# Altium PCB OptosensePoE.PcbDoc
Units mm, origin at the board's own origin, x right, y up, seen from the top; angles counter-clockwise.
Board outline 65 x 56 mm, 4 copper layers (Top Layer, Layer 1, Layer 2, Bottom Layer), stack 0.603 mm thick; 68 components, 52 nets, 267 pads, 672 vias.
Unrouted connection lines stored in the file: 1.
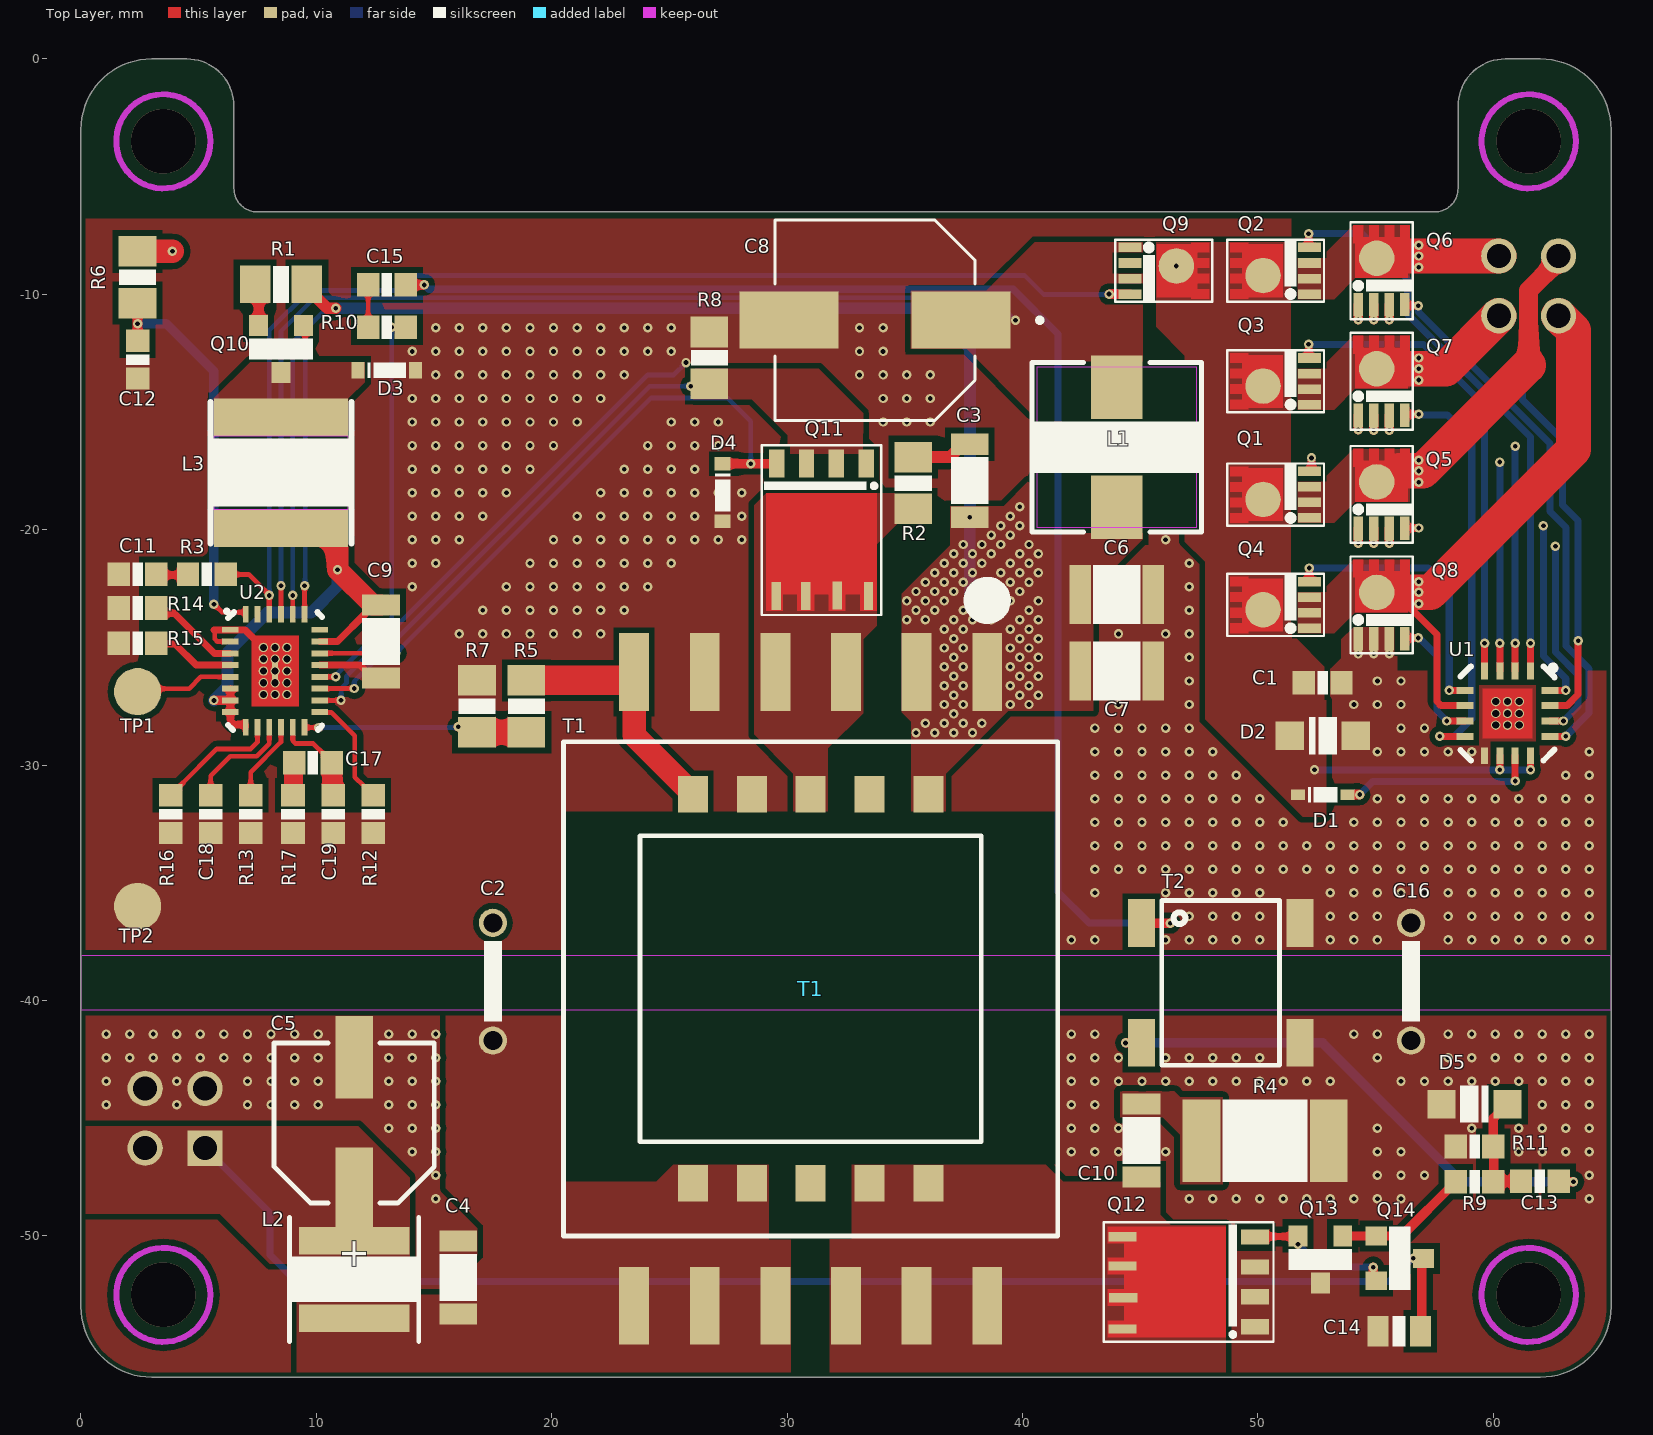
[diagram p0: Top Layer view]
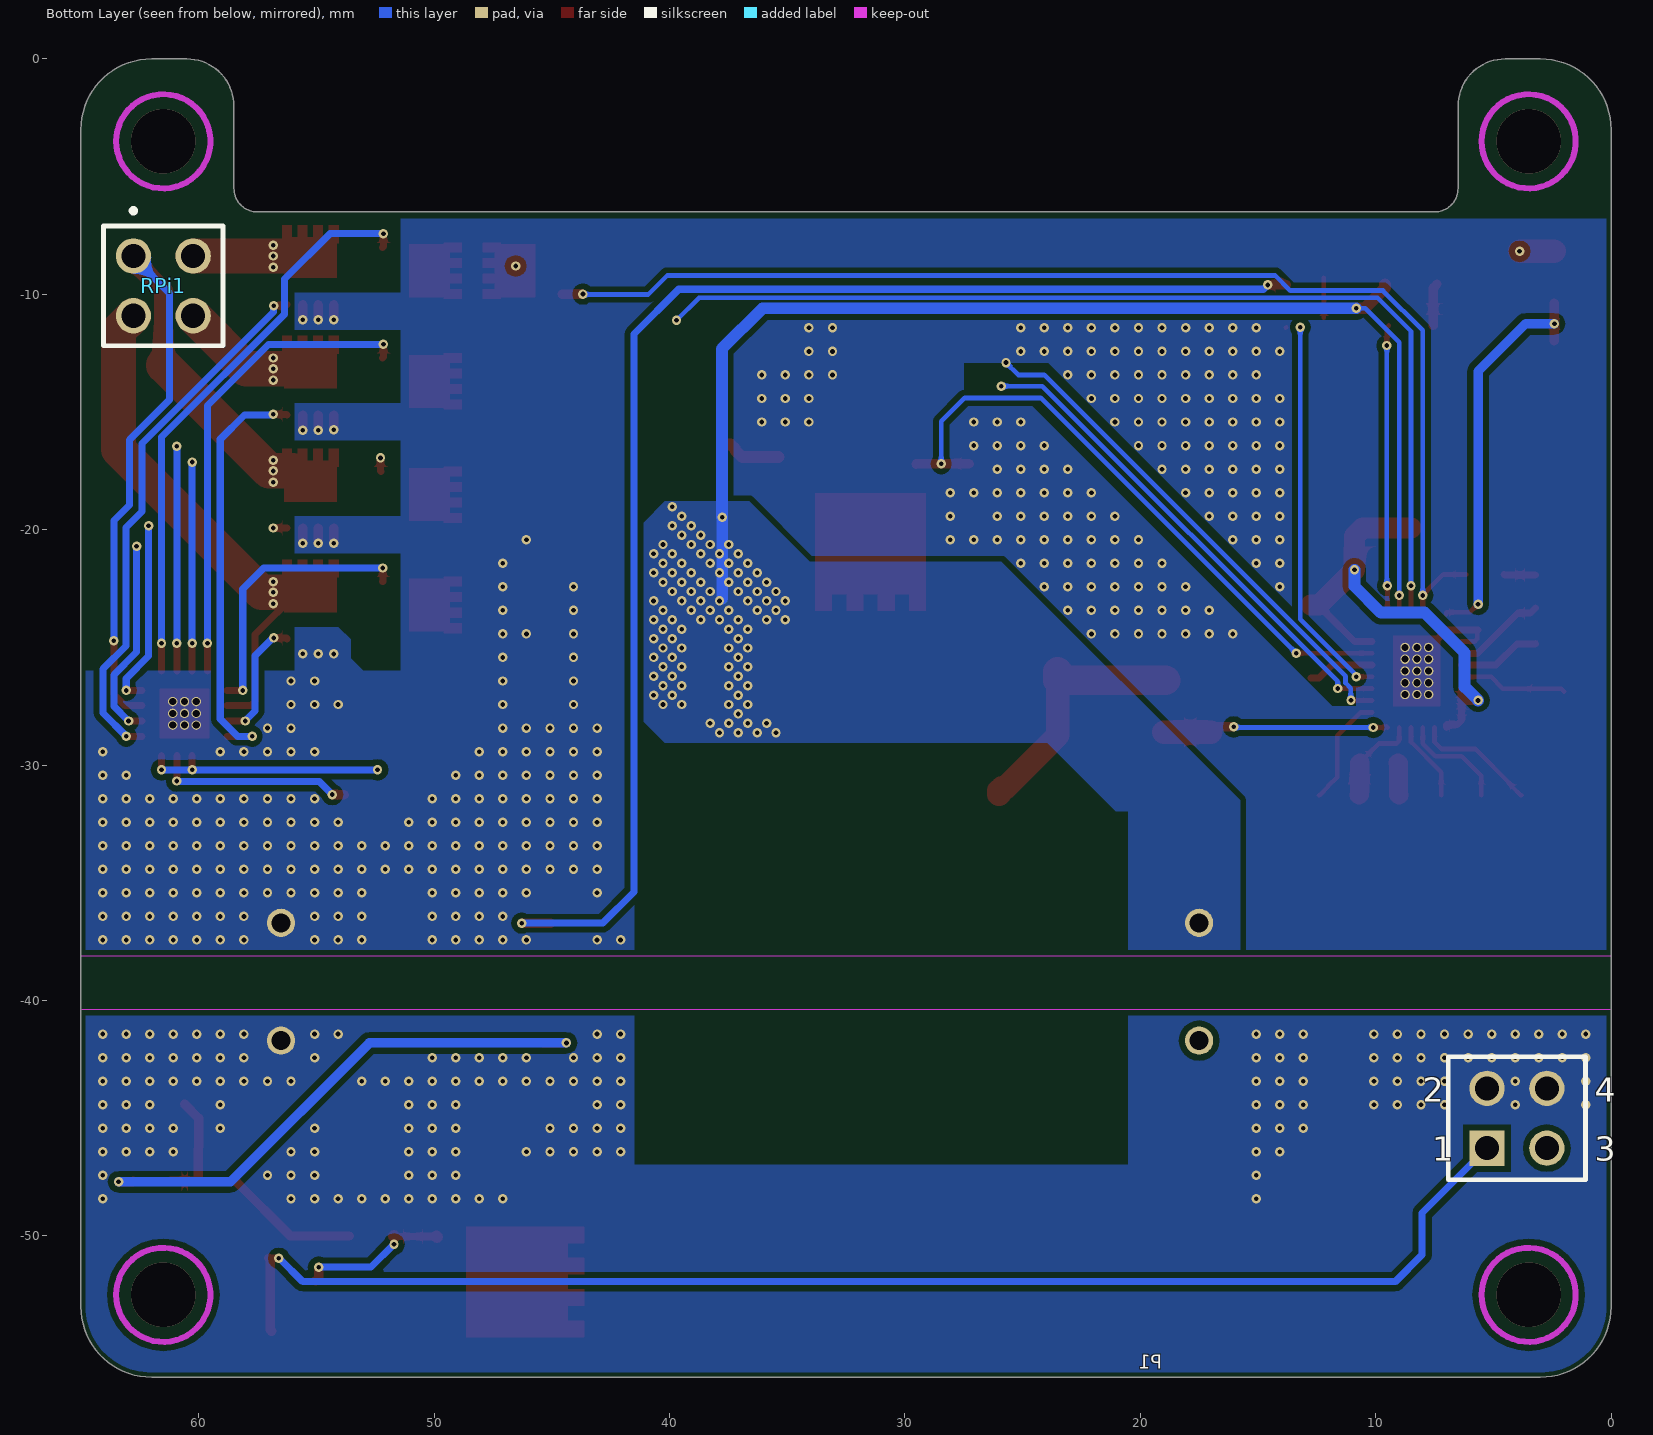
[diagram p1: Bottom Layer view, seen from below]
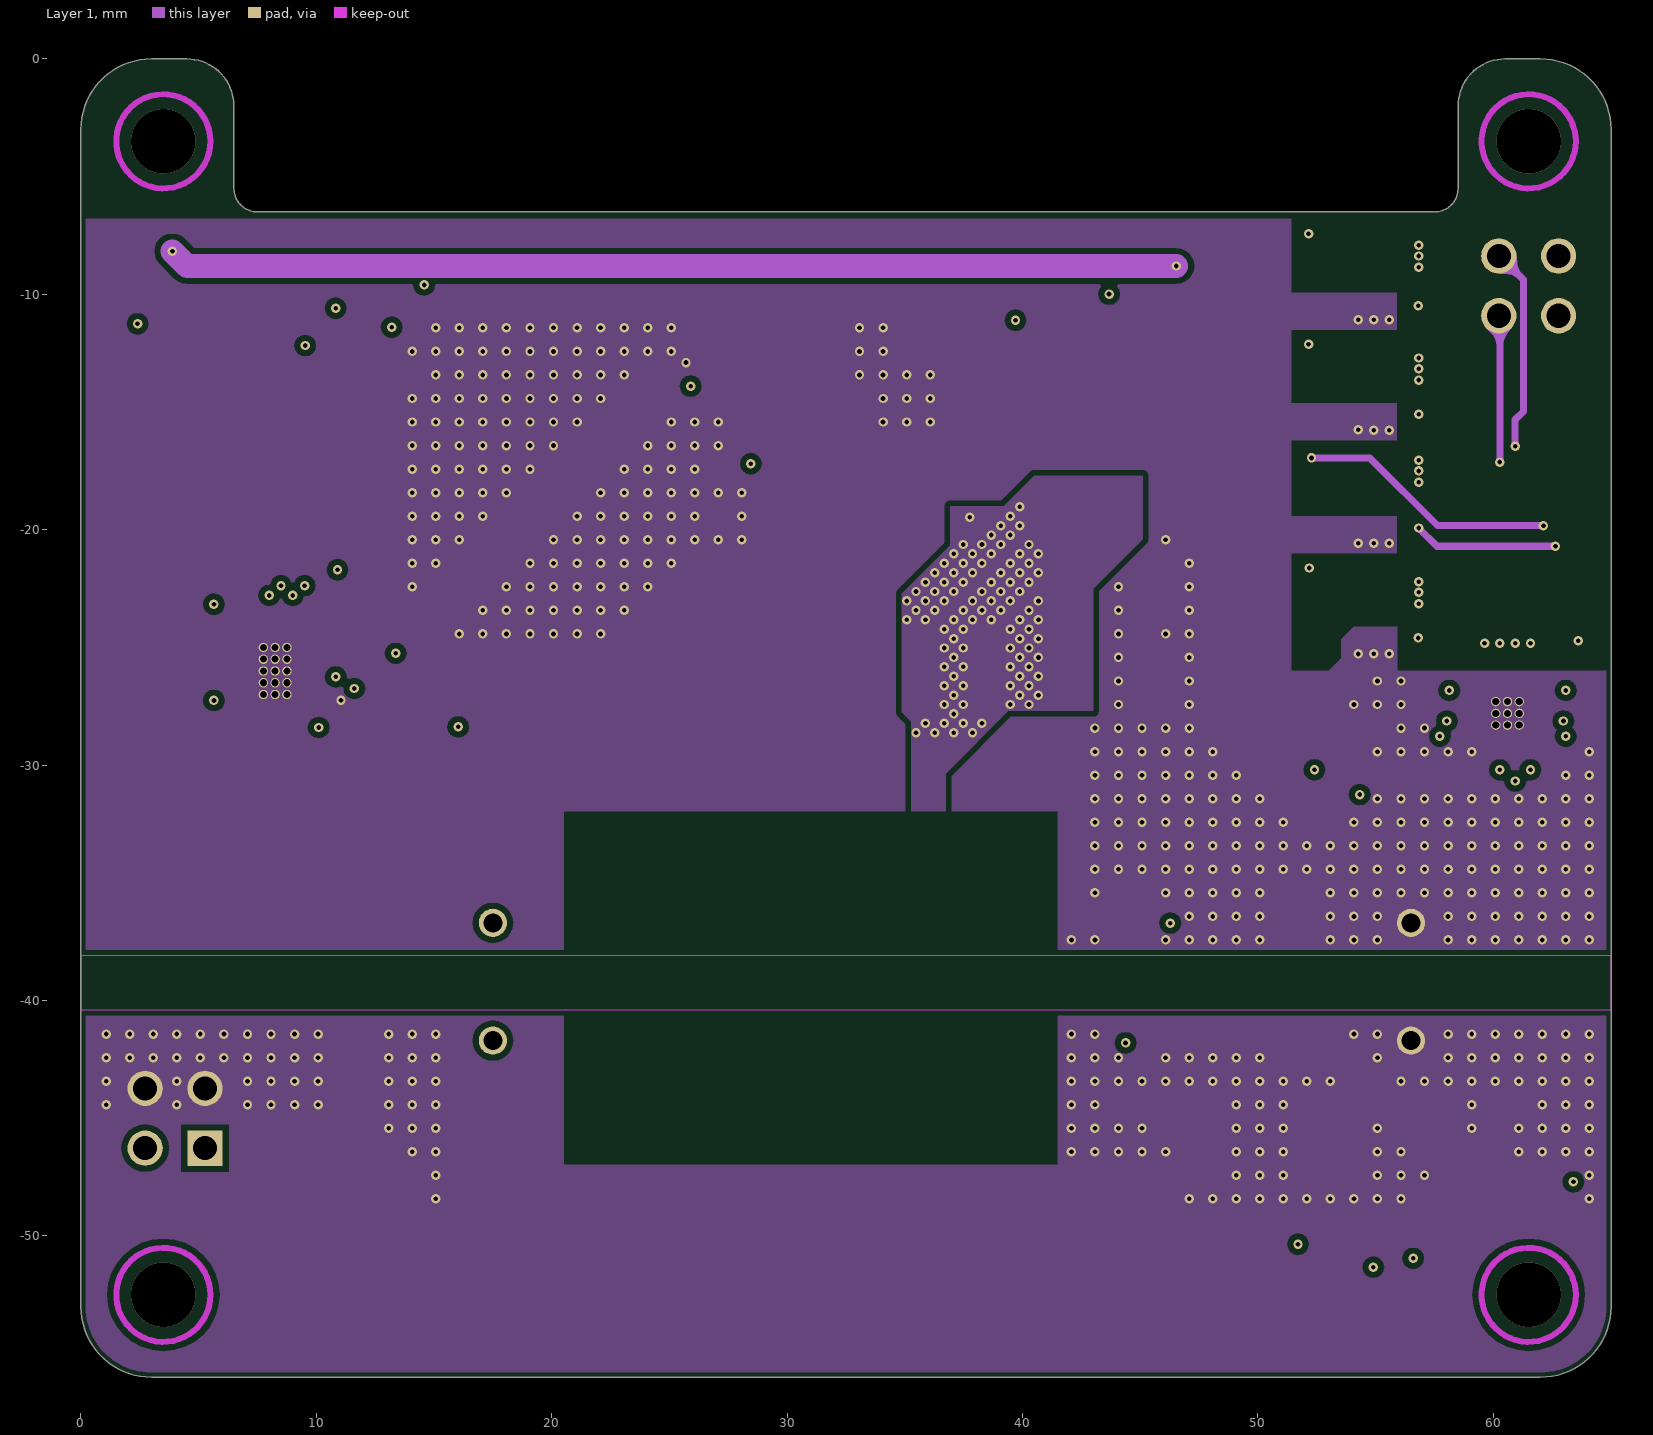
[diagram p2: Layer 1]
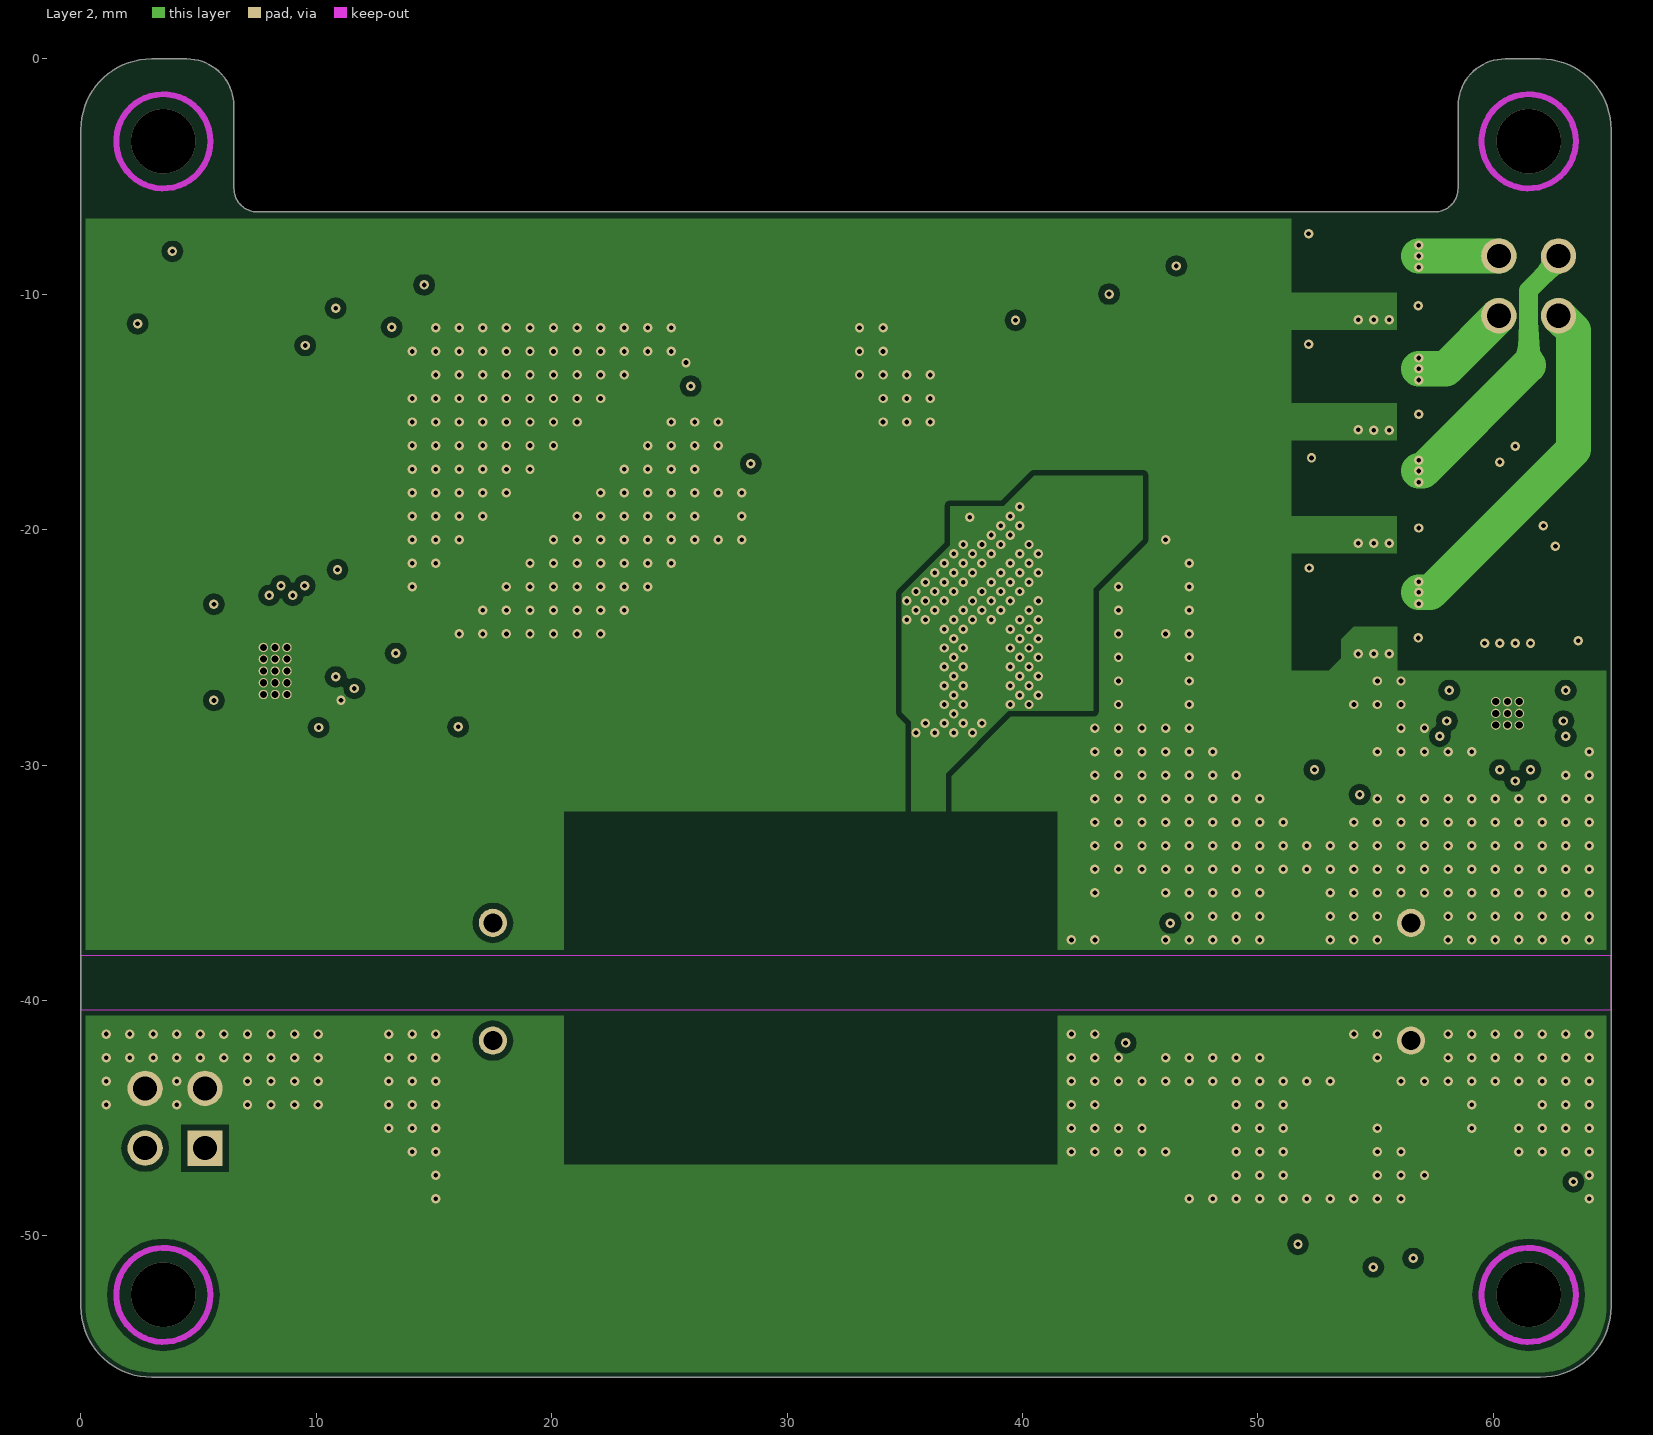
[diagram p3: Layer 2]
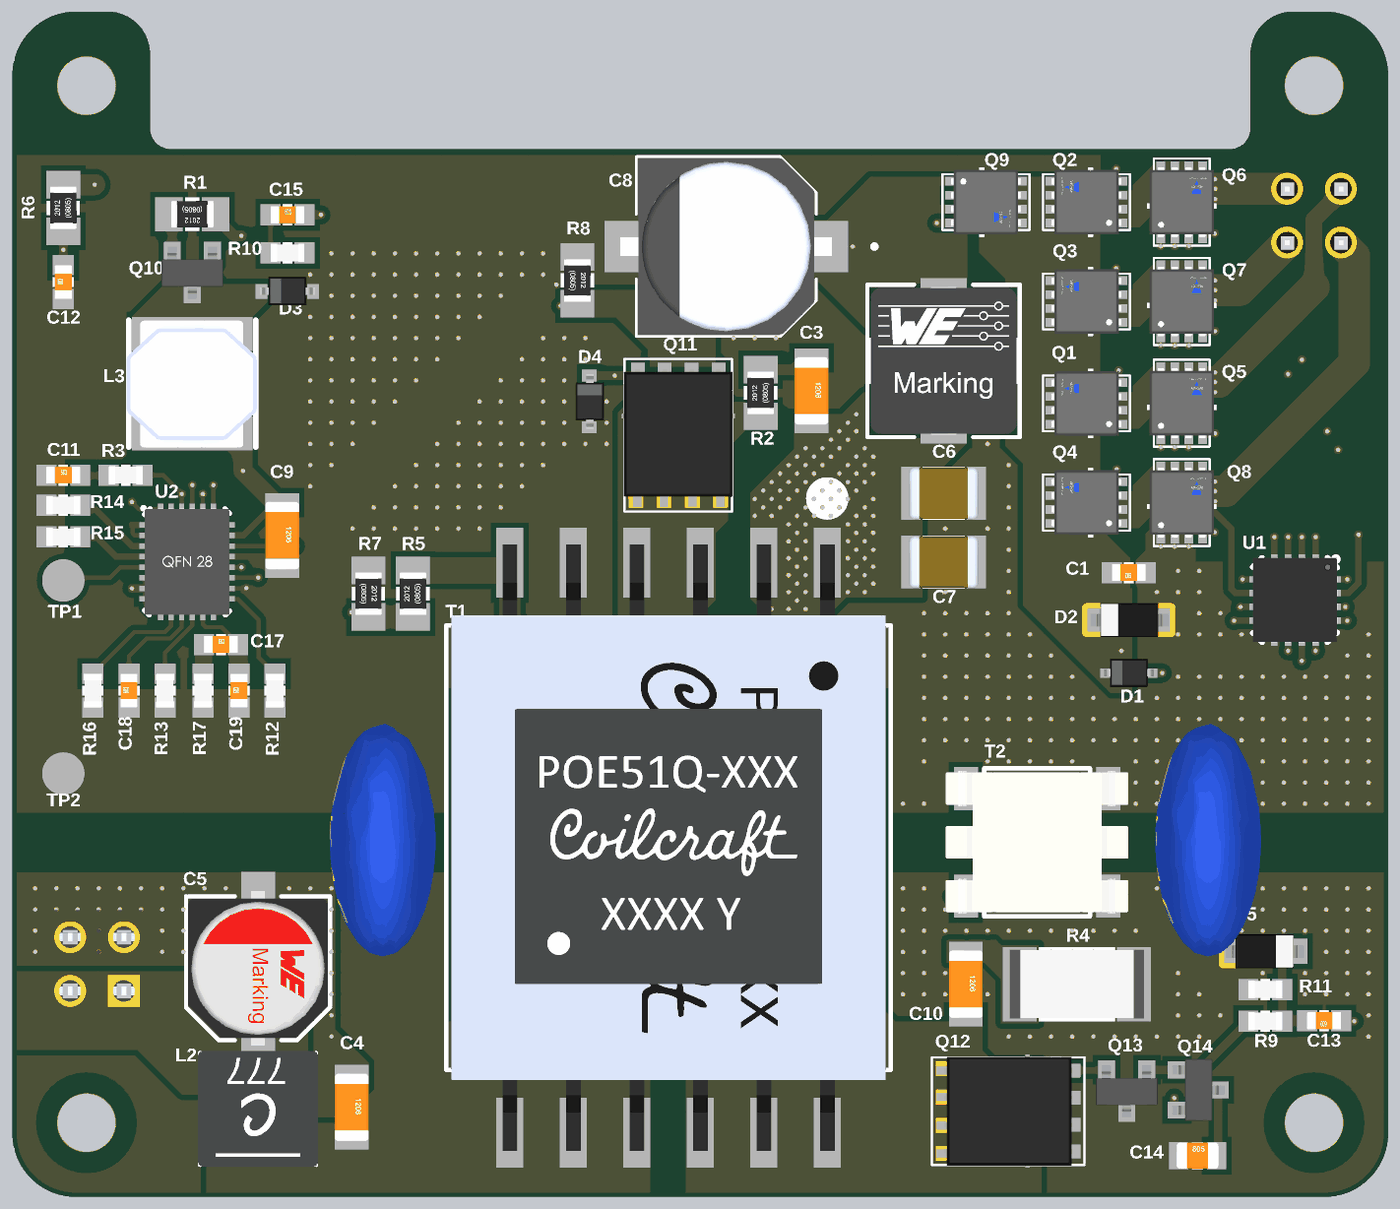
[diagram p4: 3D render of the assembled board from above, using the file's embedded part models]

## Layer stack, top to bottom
Top Solder: solder mask 0.0102, Solder Resist, Dk 3.5
Top Layer: signal copper 0.0356
Dielectric 2: core 0.0711, PP-006, Dk 4.1
Layer 1: signal copper 0.035
Dielectric 1: prepreg 0.32, FR-4, Dk 4.8
Layer 2: signal copper 0.035
Dielectric 3: core 0.0711, PP-006, Dk 4.1
Bottom Layer: signal copper 0.0356
Bottom Solder: solder mask 0.0102, Solder Resist, Dk 3.5

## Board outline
3,-56 cw(c3,-53) 0,-53 0,-3 cw(c3,-3) 3,0 4.5,0 cw(c4.5,-2) 6.5,-2 6.5,-5.5 ccw(c7.5,-5.5) 7.5,-6.5 57.5,-6.5 ccw(c57.5,-5.5) 58.5,-5.5 58.5,-2 cw(c60.5,-2) 60.5,0 62,0 cw(c62,-3) 65,-3 65,-53 cw(c62,-53) 62,-56

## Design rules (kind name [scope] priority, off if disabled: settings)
BoardOutlineClearance [All] p1: gap=0.2 ignorepadtopadclearanceinfootprint=FALSE
Clearance Clearance_VSYS [InPolygon vs InNet('VSYS')] p1: gap=0.6 ignorepadtopadclearanceinfootprint=FALSE
Clearance Clearance_2 [All] p2: gap=0.1 ignorepadtopadclearanceinfootprint=FALSE
Clearance Clearance_1 [All] p3: gap=0.1 ignorepadtopadclearanceinfootprint=FALSE
Clearance Clearance_KeepOut [All vs OnLayer('Keep-Out Layer')] p4 off: gap=1 ignorepadtopadclearanceinfootprint=FALSE except(0: Arc-Hole Track-Hole SMDPad-Hole THPad-Hole Via-Hole Fill-Hole Poly-Hole Region-Hole Text-Hole)
Clearance [All] p5: gap=0.1 ignorepadtopadclearanceinfootprint=FALSE
ComponentClearance [All] p1: gap=0 collisioncheckmode=3 verticalgap=0.254 showdistances=FALSE
FabricationTestPointUsage TestPointUsage [All] p1: valid=0 allowmultiple=FALSE
FabricationTestpoint Testpoint [All] p1: side=3 testpointundercomponent=TRUE minsize=1.016 maxsize=2.54 preferedsize=1.524 minholesize=0 maxholesize=1.016 preferedholesize=0.813 testpointgrid=0.025 allowsidetop=TRUE allowsidebottom=TRUE usegrid=TRUE gridtolerance=0
HoleSize [All] p1: absolutevalues=TRUE maxlimit=6 minlimit=0.2 maxpercent=80.000 minpercent=20.000
MinimumAnnularRing MinimumAnnularRing_Vias [isVia] p1: minimumring=0.1
MinimumAnnularRing [All] p2: minimumring=0.1
MinimumSolderMaskSliver [All] p1: minsoldermaskwidth=0
NetAntennae [All] p1 off: netantennaetolerance=0
PlaneConnect PlaneConnect_Vias [isVia] p1: planeconnectstyle=Direct reliefexpansion=0.508 reliefentries=4 reliefconductorwidth=0.254 reliefairgap=0.254
PlaneConnect [All] p2: planeconnectstyle=Direct reliefexpansion=0.508 reliefentries=4 reliefconductorwidth=0.254 reliefairgap=0.254
PolygonConnect PolygonConnect_Vias [isVia] p1: connectstyle=Direct reliefconductorwidth=0.254 reliefentries=4 polygonreliefangle="90 Angle" airgapwidth=0.254
PolygonConnect [All] p2: connectstyle=Direct reliefconductorwidth=0.254 reliefentries=4 polygonreliefangle="90 Angle" airgapwidth=0.254
RoutingVias [All] p1: holewidth=0.5 width=0.8 viastyle="Through Hole" minholewidth=0.2 minwidth=0.2 maxholewidth=0.8 maxwidth=1
SMDEntry [All] p1: side=TRUE corner=TRUE anyangle=TRUE
SMDToCorner [All] p1 off: distance=196850
SilkToSilkClearance [All] p1 off: silktosilkclearance=0.15
SilkToSolderMaskClearance SilkscreenOverComponentPads [IsPad] p1 off: minsilkscreentomaskgap=0.15 clearancetoexposedcopper=FALSE
SolderMaskExpansion [All] p1: expansion=0 istentingtop=FALSE
ViasUnderSMD [All] p1: allowed=FALSE
Width [All] p1: maxlimit=10 minlimit=0.15 preferedwidth=0.254 checkconnectedcopper=TRUE
21 further rules are at their usual default settings.

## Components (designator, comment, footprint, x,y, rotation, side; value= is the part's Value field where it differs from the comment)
C1 "47nF" C_0603 52.75,-26.5 r180 top
C2 "2.2nF" C_CK45 17.5,-36.7 r270 top
C3 "220pF" C_1206 37.757,-17.916 r270 top
C4 "10uF" C_1206 16.031,-51.769 r270 top
C5 "47uF, 35V" WCAP-ASLI_D6.3H5.5 11.606,-45.2 r270 top
C6 "2.2uF" C_1210 44,-22.75 r180 top
C7 "2.2uF" C_1210 44,-26 r180 top
C8 "10uF, 100V" CAPAE830X1080N 33.731,-11.1 r180 top
C9 "10uF" C_1206 12.75,-24.75 r270 top
C10 "330pF" C_1206 45.05,-45.95 r270 top
C11 "10nF" C_0603 2.407,-21.9 r0 top
C12 "47nF" C_0603 2.407,-12.775 r90 top
C13 "2.2nF" C_0603 61.975,-47.675 r180 top
C14 "100nF" C_0805 56,-54.05 r0 top
C15 "1uF" C_0603 13,-9.6 r0 top
C16 "2.2nF" C_CK45 56.5,-36.7 r270 top
C17 "2.2nF" C_0603 9.855,-29.896 r0 top
C18 "470nF" C_0603 5.509,-32.082 r90 top
C19 "10pF" C_0603 10.709,-32.082 r90 top
D1 "MMSZ5252BS" SOD323 52.75,-31.25 r180 top
D2 "PTVS58VS1UR" D_SOD123#1 52.75,-28.75 r180 top
D3 "BAV19WS-TP" D_SOD323 12.995,-13.225 r180 top
D4 "BAT54WS-E3-08" D_SOD323 27.257,-18.416 r90 top
D5 "BAT46W-7-F" D_SOD123#2 59.2,-44.4 r0 top
L1 "6u5" WE-HCI_7050 44,-16.5 r0 top
L1 "10uH, 3.5A" WE-HCI_7050 44,-16.5 r0 top
L2 "1.2uH" L_XAL5030 11.606,-51.844 r90 top
L3 "100uF" L_6028 8.5,-17.575 r90 top
P1 "61300421821" 61300421821 4,-45 r180 bottom locked
Q1 "SI7322ADN-T1-GE3" VISHAY_S16-2667-SINGLE_MFG 50.75,-18.509 r180 top
Q2 "SI7322ADN-T1-GE3" VISHAY_S16-2667-SINGLE_MFG 50.75,-9 r180 top
Q3 "SI7322ADN-T1-GE3" VISHAY_S16-2667-SINGLE_MFG 50.75,-13.695 r180 top
Q4 "SI7322ADN-T1-GE3" VISHAY_S16-2667-SINGLE_MFG 50.75,-23.195 r180 top
Q5 "SI7322ADN-T1-GE3" VISHAY_S16-2667-SINGLE_MFG 55.25,-18.5 r90 top
Q6 "SI7322ADN-T1-GE3" VISHAY_S16-2667-SINGLE_MFG 55.25,-9 r90 top locked
Q7 "SI7322ADN-T1-GE3" VISHAY_S16-2667-SINGLE_MFG 55.25,-13.695 r90 top
Q8 "SI7322ADN-T1-GE3" VISHAY_S16-2667-SINGLE_MFG 55.25,-23.195 r90 top
Q9 "SI7322ADN-T1-GE3" VISHAY_S16-2667-SINGLE_MFG 46,-9 r0 top
Q10 "FMMT723TA" SOT-23-3 8.5,-12.325 r180 top
Q11 "BSC190N12NS3 G" PG-TDSON-8 31.457,-20.016 r90 top
Q12 "BSC320N20NS3 G" PG-TDSON-8 47.05,-51.95 r0 top
Q13 "PBSS5140T,215" SOT-23-3 52.65,-51 r180 top
Q14 "PBSS4140T,215" SOT-23-3 56.025,-50.95 r270 top
R1 "20" R_0805 8.5,-9.575 r180 top
R2 "27" R_0805 35.357,-18.016 r90 top
R3 "3k3" R_0603 5.35,-21.9 r0 top
R4 "18" R_2512 50.3,-45.95 r180 top
R5 "7k5" R_0805 18.924,-27.5 r90 top
R6 "8R2" R_0805 2.407,-9.275 r90 top
R7 "2k" R_0805 16.822,-27.5 r270 top
R8 "40m" R_0805 26.695,-12.7 r270 top
R9 "15" R_0603 59.2,-47.7 r180 top
R10 "100" R_0603 13,-11.4 r180 top
R11 "10k" R_0603 59.2,-46.2 r0 top
R12 "24k" R_0603 12.409,-32.082 r90 top
R13 "5k23" R_0603 7.209,-32.082 r90 top
R14 "47R5" R_0603 2.407,-23.325 r0 top
R15 "35R7" R_0603 2.407,-24.825 r0 top
R16 "107k" R_0603 3.809,-32.082 r90 top
R17 "160k" R_0603 9.009,-32.082 r90 top
RPi1 "RPi" "RPi - THT Hybrid - NoneHeader" 32.5,-3.5 r180 bottom locked
T1 "POE51Q-24ED" POEXXQ-24E 31,-39.5 r270 top locked
T1 "POE300PL_24" TRANSFORMER_COILCRAFT_POE300 31,-39.5 r270 top locked
T2 "PE-68386NL" T_PE-68386NL 48.415,-39.25 r0 top
TP1 "TP" TESTPOINT#1 2.407,-26.875 r180 top
TP2 "TP" TESTPOINT#2 2.407,-35.425 r90 top
U1 "LT4321" IC_QFN_16_PLASTIC 60.6,-27.8 r270 top
U2 "LT4295" IC_QNF_28_PLASTIC 8.25,-26 r0 top locked

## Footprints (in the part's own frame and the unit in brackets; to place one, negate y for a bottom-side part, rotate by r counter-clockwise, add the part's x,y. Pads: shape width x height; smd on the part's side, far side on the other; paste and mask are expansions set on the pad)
61300421821 [mm] "Socket Header, Pitch 2.54 mm, THT, Vertical, dual row, 4p"
  rect 1.5x1.5 hole 1.02: 1(-1.27,-1.27)
  round 1.5 hole 1.02: 2(-1.27,1.27) 3(1.27,-1.27) 4(1.27,1.27)
  silkscreen extent -2.92,-2.62 2.92,2.62, body extent -2.79,-2.54 2.79,2.54, height 8.45
C_0603 [mm]
  rect 0.95x1 smd: 1(-0.8,0) 2(0.8,0)
  silkscreen extent -0.23,-0.5 0.23,0.5, body extent -0.8,-0.4 0.8,0.4, height 0.3
C_0805 [mm]
  rect 0.9x1.3 smd: 1(-0.9,0) 2(0.9,0)
  silkscreen extent -0.28,-0.65 0.28,0.65, body extent -1,-0.62 1,0.62, height 0.78
C_1206 [mm]
  rect 0.9x1.6 smd: 1(-1.55,0) 2(1.55,0)
  silkscreen extent -1,-0.8 1,0.8, body extent -1.6,-0.8 1.6,0.8, height 1
C_1210 [mm]
  rect 0.9x2.5 smd: 1(-1.55,0) 2(1.55,0)
  silkscreen extent -1,-1.25 1,1.25, body extent -1.65,-1.25 1.65,1.25, height 2.79
C_CK45 [mm]
  round 1.2 hole 0.8: 1(0,0) 2(5,0)
  silkscreen extent 0.76,-0.38 4.19,0.38, body extent -3.05,-2.5 7.94,2.5, height 12.5
CAPAE830X1080N [mm]
  rect 4.21x2.42 smd: 1(-3.65,0) 2(3.65,0)
  silkscreen extent -7.1,-4.25 4.25,4.25, body extent -5,-4.15 5,4.15, height 10.5
D_SOD123#1 [mm]
  rect 1.2x1.2 smd paste-0.05 mask+0.2: A(-1.4,0) K(1.4,0)
  silkscreen extent -0.61,-0.79 0.58,0.79, body extent -1.88,-0.8 1.82,0.8, height 1.27
D_SOD123#2 [mm]
  rect 1.2x1.2 smd paste-0.05 mask+0.2: A(-1.4,0)
  rect 1.2x1.2 smd paste+0: K(1.4,0)
  silkscreen extent -0.61,-0.79 0.58,0.79, body extent -1.88,-0.8 1.82,0.8, height 1.27
D_SOD323 [mm]
  rect 0.56x0.69 smd: A(-1.22,0) K(1.22,0)
  silkscreen extent -0.81,-0.33 0.81,0.33, body extent -1.3,-0.7 1.3,0.65, height 1.1
IC_QFN_16_PLASTIC [mm]
  rect 0.72x0.3 smd: 1(-1.8,0.975) 2(-1.8,0.325) 3(-1.8,-0.325) 4(-1.8,-0.975) 9(1.8,-0.975) 10(1.8,-0.325) 11(1.8,0.325) 12(1.8,0.975)
  rect 0.3x0.72 smd: 5(-0.975,-1.8) 6(-0.325,-1.8) 7(0.325,-1.8) 8(0.975,-1.8) 13(0.975,1.8) 14(0.325,1.8) 15(-0.325,1.8) 16(-0.975,1.8)
  round 0.4 hole 0.3: 9(-0.5,0.5) 9(-0.5,0) 9(-0.5,-0.5) 9(0,0.5) 9(0,0) 9(0,-0.5) 9(0.5,0.5) 9(0.5,0) 9(0.5,-0.5)
  Top Layer region: -1.05,-1.05 -1.05,1.05 1.05,1.05 1.05,-1.05
  silkscreen extent -2.03,-2 2,2.03, body extent -2,-2 2,2, height 0.92
IC_QNF_28_PLASTIC [mm]
  rect 0.7x0.25 smd: 1(-1.9,1.75) 2(-1.9,1.25) 3(-1.9,0.75) 4(-1.9,0.25) 5(-1.9,-0.25) 6(-1.9,-0.75) 7(-1.9,-1.25) 8(-1.9,-1.75) 15(1.9,-1.75) 16(1.9,-1.25) 17(1.9,-0.75) 18(1.9,-0.25) 19(1.9,0.25) 20(1.9,0.75) 21(1.9,1.25) 22(1.9,1.75)
  rect 0.25x0.7 smd: 9(-1.25,-2.4) 10(-0.75,-2.4) 11(-0.25,-2.4) 12(0.25,-2.4) 13(0.75,-2.4) 14(1.25,-2.4) 23(1.25,2.4) 23(1.25,2.4) 24(0.75,2.4) 25(0.25,2.4) 26(-0.25,2.4) 27(-0.75,2.4) 28(-1.25,2.4)
  round 0.4 hole 0.3: 19(-0.5,-1) 19(-0.5,-0.5) 19(-0.5,0) 19(-0.5,0.5) 19(-0.5,1) 19(0,-1) 19(0,-0.5) 19(0,0) 19(0,0.5) 19(0,1) 19(0.5,-1) 19(0.5,-0.5) 19(0.5,0) 19(0.5,0.5) 19(0.5,1)
  rect 0.25x0.7 smd paste+0 mask+0: 29(0,0)
  Top Layer region: -1,1.5 -1,-1.5 1,-1.5 1,1.5
  silkscreen extent -2.08,-2.5 2,2.56, body extent -2.01,-2.5 2,2.51, height 0.7
L_6028 [mm] "NRS6028T101MMGJ"
  rect 1.6x5.7 smd: 1(-2.35,0) 2(2.35,0)
  silkscreen extent -3,-3 3,3, body extent -3.03,-3.05 2.97,3.1, height 2.58
L_XAL5030 [mil]
  rect 46x185 smd: 1(-65,0) 2(65,0)
  silkscreen extent -104,-108 104,108, body extent -108,-112 108,112, height 118
PG-TDSON-8 [mm]
  rect 1.2x0.65 smd: 1(2.825,-1.905) 2(2.825,-0.635) 3(2.825,0.635) 4(2.825,1.905)
  rect 1.2x0.4 smd mask+0: 5(-2.8,1.925) 6(-2.8,0.675) 7(-2.775,-0.675) 8(-2.8,-2)
  Top Layer region: -3.425,-2.35 1.575,-2.35 1.575,2.35 -3.425,2.35 -3.425,1.65 -2.725,1.65 -2.725,1.02 -3.425,1.02 -3.425,0.315 -2.725,0.315 -2.725,-0.315 -3.425,-0.315 -3.425,-1.02 -2.725,-1.02 -2.725,-1.65 -3.425,-1.65
  silkscreen extent -3.61,-2.54 3.61,2.54, body extent -3.02,-2.68 3.13,2.67, height 1
POEXXQ-24E [mm] "Coilcraft Flyback Transformer"
  rect 1.55x1.27 smd: 1(-8.268,5) 2(-8.268,2.5) 3(-8.268,0) 4(-8.268,-2.5) 5(-8.268,-5) 6(8.268,-5) 7(8.268,-2.5) 8(8.268,0) 9(8.268,2.5) 10(8.268,5)
  silkscreen extent -6.5,-7.25 6.5,7.25, body extent -8.55,-7.25 8.45,7.25, height 13.87
R_0603 [mm]
  rect 0.95x1 smd: 1(-0.8,0) 2(0.8,0)
  silkscreen extent -0.23,-0.5 0.23,0.5, body extent -0.8,-0.43 0.8,0.43, height 0.53
R_0805 [mm]
  rect 1.3x1.6 smd: 1(-1.1,0) 2(1.1,0)
  silkscreen extent -0.33,-0.79 0.33,0.79, body extent -1,-0.63 1,0.62, height 0.45
R_2512 [mm]
  rect 1.6x3.5 smd: 1(-2.7,0) 2(2.7,0)
  silkscreen extent -1.8,-1.75 1.8,1.75, body extent -3.17,-1.63 3.18,1.63, height 0.63
"RPi - THT Hybrid - NoneHeader" [mm] "Socket Header, Pitch 2.54 mm, SMT, Vertical, dual row, 40p"
  round 1.5 hole 1.02: 1_PoE(-30.27,-4.87) 2_PoE(-27.73,-4.87) 3_PoE(-27.73,-7.41) 4_PoE(-30.27,-7.41)
  Top Layer pour cut-out: -29,-51 -29.765,-50.848 -30.414,-50.414 -30.848,-49.765 -31,-49 -31,-49 -30.848,-48.235 -30.414,-47.586 -29.765,-47.152 -29,-47 -29,-47 -28.235,-47.152 -27.586,-47.586 -27.152,-48.235 -27,-49 -27,-49 -27.152,-49.765 -27.586,-50.414 -28.235,-50.848 -29,-51
  Top Layer pour cut-out: 29,-51 28.235,-50.848 27.586,-50.414 27.152,-49.765 27,-49 27,-49 27.268,-48 28,-47.268 29,-47 29,-47 29.765,-47.152 30.414,-47.586 30.848,-48.235 31,-49 31,-49 30.848,-49.765 30.414,-50.414 29.765,-50.848 29,-51
  Top Layer pour cut-out: -29,-2 -29.765,-1.848 -30.414,-1.414 -30.848,-0.765 -31,0 -31,0 -30.848,0.765 -30.414,1.414 -29.765,1.848 -29,2 -29,2 -28.235,1.848 -27.586,1.414 -27.152,0.765 -27,0 -27,0 -27.152,-0.765 -27.586,-1.414 -28.235,-1.848 -29,-2
  Top Layer pour cut-out: 29,-2 28.235,-1.848 27.586,-1.414 27.152,-0.765 27,0 27,0 27.268,1 28,1.732 29,2 29,2 29.765,1.848 30.414,1.414 30.848,0.765 31,0 31,0 30.848,-0.765 30.414,-1.414 29.765,-1.848 29,-2
  Bottom Layer pour cut-out: -29,-51 -29.868,-50.802 -30.564,-50.247 -30.95,-49.445 -30.95,-48.555 -30.564,-47.753 -29.868,-47.198 -29,-47 -29,-47 -28,-47.268 -27.268,-48 -27,-49 -27,-49 -27.152,-49.765 -27.586,-50.414 -28.235,-50.848 -29,-51
  Bottom Layer pour cut-out: 29,-51 28.235,-50.848 27.586,-50.414 27.152,-49.765 27,-49 27,-49 27.268,-48 28,-47.268 29,-47 29,-47 29.765,-47.152 30.414,-47.586 30.848,-48.235 31,-49 31,-49 30.848,-49.765 30.414,-50.414 29.765,-50.848 29,-51
  Bottom Layer pour cut-out: 29,-2 28.235,-1.848 27.586,-1.414 27.152,-0.765 27,0 27,0 27.152,0.765 27.586,1.414 28.235,1.848 29,2 29,2 29.765,1.848 30.414,1.414 30.848,0.765 31,0 31,0 30.848,-0.765 30.414,-1.414 29.765,-1.848 29,-2
  Bottom Layer pour cut-out: -29,-2 -29.765,-1.848 -30.414,-1.414 -30.848,-0.765 -31,0 -31,0 -30.848,0.765 -30.414,1.414 -29.765,1.848 -29,2 -29,2 -28.235,1.848 -27.586,1.414 -27.152,0.765 -27,0 -27,0 -27.152,-0.765 -27.586,-1.414 -28.235,-1.848 -29,-2
  Keep-Out Layer circle w0.254: c-29,-49 r2
  Keep-Out Layer circle w0.254: c29,-49 r2
  Keep-Out Layer circle w0.254: c29,0 r2
  Keep-Out Layer circle w0.254: c-29,0 r2
  silkscreen extent -31.54,-8.68 -26.46,-2.85, body extent -31.81,-8.7 -26.22,-3.62, height 18.51
SOD323 [mm]
  rect 0.59x0.45 smd: A(-1.055,0) K(1.055,0)
  silkscreen extent -0.64,-0.33 0.64,0.33, body extent -1.3,-0.69 1.3,0.66
SOT-23-3 [mm]
  rect 0.8x0.9 smd: B(-0.95,-1) C(0,1) E(0.95,-1)
  silkscreen extent -1.35,-0.45 1.35,0.45, body extent -1.46,-1.22 1.46,1.25, height 1
T_PE-68386NL [mil]
  rect 45x80 smd: 1(-132.5,100) 2(-132.5,-100) 3(132.5,-100) 4(132.5,100)
  silkscreen extent -98,-138 98,138, body extent -170,-132 170,133, height 98
TESTPOINT#1 [mm]
  round 2 smd paste+0 mask+0: 1(0,0)
TESTPOINT#2 [mm]
  round 2 smd paste+0 mask+0: 1(-0.575,0)
TRANSFORMER_COILCRAFT_POE300 [mm] "POE300F-24L"
  rect 3.3x1.27 smd: 1(-13.46,7.5) 1(-13.46,7.5) 2(-13.46,4.5) 3(-13.46,1.5) 4(-13.46,-1.5) 5(-13.46,-4.5) 6(-13.46,-7.5) 7(13.46,-7.5) 8(13.46,-4.5) 9(13.46,-1.5) 10(13.46,1.5) 11(13.46,4.5) 12(13.46,7.5)
  silkscreen extent -17,-10.5 10.5,10.5, body extent -14.32,-10.28 14.33,10.29, height 11.38
VISHAY_S16-2667-SINGLE_MFG [mil]
  rect 39x16 smd paste+0 mask+0: 1(-56.5,39) 2(-56.5,13) 3(-56.5,-13) 4(-56.5,-39)
  round 59.4 smd paste+0 mask+0: 5-6-7-8(21,8)
  Top Layer region: -12,44 46,44 46,47 76,47 76,31 56,31 56,21 76,21 76,5 56,5 56,-5 76,-5 76,-21 56,-21 56,-31 76,-31 76,-47 46,-47 46,-44 -12,-44
  silkscreen extent -81,-52 81,52, body extent -80,-71 80,71, height 10
WCAP-ASLI_D6.3H5.5 [mm] "Aluminium Electrolytic V-Chip SMT Capacitors, 6.3x5.5mm"
  rect 3.5x1.6 smd: 1(2.8,0) 2(-2.8,0)
  silkscreen extent -3.4,-3.4 3.4,3.4, body extent -3.65,-3.3 3.65,3.3, height 5.5
WE-HCI_7050 [mm] "SMT Flat Wire High Current Inductor, body 6.9x6.9mm"
  rect 2.2x2.7 smd: 1(0,2.55) 2(0,-2.55)
  silkscreen extent -3.6,-3.6 3.6,3.6, body extent -3.45,-3.5 3.45,3.5, height 5

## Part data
C1 C12: library part C_47n_0603_100V_10%, "885012206118"
C2 C16: library part C_2n2_2kV_10%, "CK45-B3DD222KYVNA"
C3: library part C_220p_1206_630V_5%, "1206N221J631CT"
C4: library part C_10u_1206_50V_10%, "UMK316BBJ106KL-T"
C5: library part 865080543009, "WCAP-ASLI Aluminum Electrolytic Capacitor, V-Chip, SMT, D6.3xH5.5mm, 47uF, 35V", Capacitance=47uF, Capacitance Tolerance=+/-20%, Leakage Current=16.45uA, Manufacturer="Wurth Elektronik", Operating Temperature="-55 to +105degC", Rated Voltage=35VDC, Ripple Current=240mA
C6 C7: library part C_2u2_1210_100V_10%, "HMK325B7225KM-T"
C8: library part C_10uF_100V_Elko, "EEE-2AA100P", Capacitance=47uF, Capacitance Tolerance=+/-20%, Leakage Current=16.45uA, Manufacturer="Wurth Elektronik", Manufacturer Part Number=865080543009, Operating Temperature="-55 to +105degC", Rated Voltage=35VDC, Ripple Current=240mA
C9: library part C_10u_1206_10V_10%, "LMK316B7106KL-T"
C10: library part C_330p_1206_100V_5%, "885012008070"
C11: library part C_10n_0603_100V_10%, "C1608X7R2A103K080AA"
C13: library part C_2n2_0603_50V_10%, "06035C222KAT4A"
C14: library part C_0u1_0805_50V_10%, "885012207098"
C15: library part C_1u_0603_25V_10%, "TMK107B7105KA-T"
C17: library part C_3n3_0603_50V_100%, "VJ0603Y332KXACW1BC"
C18: library part C_470n_0603_50V_10%, "UMK107B7474KA-TR"
C19: library part C_10p_0603_50V_10%, "06035C100K4T4A"
D1: library part D_Zener_SOD-323, "24V_MMSZ5252BS"
D2: library part D_TVS_SOD123, "TVS_58V_SOD123_PTVS58VS1UR"
D3: library part D_Schottky_SOD323_BAV19WS-TP
D4: library part D_SOD323_BAT54WS-E3-08
D5: library part D_Schottky_SOD123
L1: library part L_6u5, "744314650"
L1: library part 744314101, "WE-HCI SMT Flat Wire High Current Inductor, size 7050, 10uH, 3.5A", DC Resistance=33mOhm, Inductance=10uH, Manufacturer="Wurth Elektronik", Operating Temperature="-40 to +150degC", Rated Current=3.5A, Rated Inductance=7.5uH, Saturation Current=4A, Self Resonant Frequency=40MHz
L2: library part L_1u2, "XAL5030-122MEC"
L3: library part L_100u, "NRS6028T101MMGJ"
P1: "WR-PHD Socket Header, THT, pitch 2.54mm, Dual Row, Vertical, 4p", Contact Resistance=20mOhm, Manufacturer="Wurth Elektronik", Operating Temperature="-40 to +125degC", Rated Current=3A, Withstanding Voltage=500VAC, Working Voltage=250VAC
Q10: library part Q_PNP-Transistor_FMMT723TA, "PNP_FMMT723TA"
Q11: library part Q_N-Channel_MOSFET_PG-TDSON-8, "N-Channel MOSFET"
Q12: library part "Q_N-Channel_MOSFET_PG-TDSON-8_BSC320N20NS3 G"
Q13: library part Q_PNP-Transistor_PBSS5140T,215, "PNP_PBSS5140T,215"
Q14: library part Q_NPN-Transistor_PBSS4140T,215
R1: library part R_20_0805, "CRCW080520R0JNEA"
R2: library part R_27_0805_5%_0W5, "ERJ-P06J270V"
R3: library part R_3k3_0603_1%, "CRCW06033K30FKEAC"
R4: library part R_18_2512_1%_1W, "ERJ-1TNF18R0U"
R5: library part R_7k5_0805_1%, "ERJ-P06F7501V"
R6: library part R_8R2_0805, "CRCW08058R20JNEA"
R7: library part R_2k_1%_0W5, "AC0805FR-7W2KL"
R8: library part R_40m_0805_0W5_1%, "WSLP0805R0400FEA"
R9: library part R_15_0603_1%, "CRCW060315R0FKEB"
R10: library part R_100_0603_1%, "CRCW0603100RFKEAC"
R11: library part R_10k_0603_1%, "CRCW060310K0FKEA"
R12: library part R_24k_0603_1%, "CRCW060324K0FKEA"
R13: library part R_5k23_0603_1%, "CRCW06035K23FKEA"
R14: library part R_47R5_0603
R15: library part R_35R7_0603
R16: library part R_107k_0603_1%, "CRCW0603107KFKEA"
R17: library part R_160k_0603_1%, "CRCW0603160KFKEA"
RPi1: "WR-PHD Socket Header, SMT, pitch 2.54mm, Dual Row, Vertical, 40pin", Contact Resistance=20mOhm, Operating Temperature="-40 to +105degC", Part Number=61004021821, Rated Current=3A, Withstanding Voltage=600VAC, Working Voltage=250VAC
T1: library part T_Transformer_POE51Q-24ED, "Transformer_PoE_24V_51W"
T1: library part T_Transformer_PoE30W_24V, "Transformer_PoE_24V_30W"
T2: library part T_Transformer_Gatedrive_PE-68386NL, "Transformer_Gatedrive_PE-68386NL"
TP1 TP2: library part Testpoint, "Testpoint"
U1: library part IC_LT4321, "LT4321IUF"
U2: library part IC_LT4295

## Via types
v1: diameter 0.4, hole 0.2, Top Layer to Bottom Layer, tented both sides, 668 vias
v2: diameter 2.75, hole 2.75, Top Layer to Bottom Layer, 4 vias

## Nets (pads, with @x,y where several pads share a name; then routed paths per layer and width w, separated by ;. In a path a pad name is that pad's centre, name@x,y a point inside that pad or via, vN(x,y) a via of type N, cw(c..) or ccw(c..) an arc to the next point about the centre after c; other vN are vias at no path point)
BG12: Q5.4 U1.14 | length 15.4
  Top Layer w0.3: Q5.4 56.251,-19.925 v1(56.825,-19.925) ; U1.14 v1(62.975,-28.125)
  Layer 1 w0.3: v1(56.825,-19.925) 57.601,-20.701 v1(62.636,-20.701)
  Bottom Layer w0.3: v1(62.636,-20.701) 62.636,-25.197 63.602,-26.162 63.602,-27.498 v1(62.975,-28.125)
BG36: Q6.4 U1.13 | length 23
  Top Layer w0.3: Q6.4 56.286,-10.48 v1(56.805,-10.48) ; U1.13 v1(63.075,-28.775) v1@63.1,-28.8
  Bottom Layer w0.3: v1(56.805,-10.48) 56.824,-10.499 56.824,-10.749 62.408,-16.332 62.408,-19.228 63.086,-19.906 63.086,-24.936 64.059,-25.908 64.059,-27.791 v1(63.075,-28.775)
BG45: Q7.4 U1.8 | length 17.9
  Top Layer w0.3: Q7.4 56.271,-15.1 v1(56.825,-15.1) ; v1@57.7,-28.8 v1(57.725,-28.775) U1.8
  Bottom Layer w0.3: v1(56.825,-15.1) 56.844,-15.119 58.045,-15.119 59.08,-16.154 59.08,-28.044 58.349,-28.775 v1(57.725,-28.775)
BG78: Q8.4 U1.7 | length 5.4
  Top Layer w0.3: Q8.4 56.274,-24.597 v1(56.804,-24.597) ; v1@58,-28.1 v1(58.025,-28.125) U1.7
  Bottom Layer w0.3: v1@56.88,-24.63 57.6,-25.35 57.6,-27.7 v1(58.025,-28.125)
GND: C4.1 C5.2 C14.1 C16.2 D5.A P1.2 P1.4 Q12.1 Q12.2 Q12.3 Q13.C R4.1 R11.1 T2.3
  other v1: 15.075,-48.425 47.075,-48.425 48.075,-48.425 49.075,-48.425 50.075,-48.425 51.075,-48.425 52.075,-48.425 53.075,-48.425 54.075,-48.425 55.075,-48.425 56.075,-48.425 64.075,-48.425 15.075,-47.425 49.075,-47.425 50.075,-47.425 51.075,-47.425 55.075,-47.425 56.075,-47.425 57.075,-47.425 64.075,-47.425 14.075,-46.425 15.075,-46.425 42.075,-46.425 43.075,-46.425 44.075,-46.425 45.075,-46.425 46.075,-46.425 49.075,-46.425 50.075,-46.425 51.075,-46.425 55.075,-46.425 56.075,-46.425 61.075,-46.425 62.075,-46.425 63.075,-46.425 64.075,-46.425 13.075,-45.425 14.075,-45.425 15.075,-45.425 42.075,-45.425 43.075,-45.425 44.075,-45.425 45.075,-45.425 49.075,-45.425 50.075,-45.425 51.075,-45.425 55.075,-45.425 59.075,-45.425 61.075,-45.425 62.075,-45.425 63.075,-45.425 64.075,-45.425 1.075,-44.425 4.075,-44.425 7.075,-44.425 8.075,-44.425 9.075,-44.425 10.075,-44.425 13.075,-44.425 14.075,-44.425 15.075,-44.425 42.075,-44.425 43.075,-44.425 49.075,-44.425 50.075,-44.425 51.075,-44.425 59.075,-44.425 62.075,-44.425 63.075,-44.425 64.075,-44.425 1.075,-43.425 4.075,-43.425 7.075,-43.425 8.075,-43.425 9.075,-43.425 10.075,-43.425 13.075,-43.425 14.075,-43.425 15.075,-43.425 42.075,-43.425 43.075,-43.425 44.075,-43.425 45.075,-43.425 46.075,-43.425 47.075,-43.425 48.075,-43.425 49.075,-43.425 50.075,-43.425 51.075,-43.425 52.075,-43.425 53.075,-43.425 56.075,-43.425 57.075,-43.425 58.075,-43.425 59.075,-43.425 60.075,-43.425 61.075,-43.425 62.075,-43.425 63.075,-43.425 64.075,-43.425 1.075,-42.425 2.075,-42.425 3.075,-42.425 4.075,-42.425 5.075,-42.425 6.075,-42.425 7.075,-42.425 8.075,-42.425 9.075,-42.425 10.075,-42.425 13.075,-42.425 14.075,-42.425 15.075,-42.425 42.075,-42.425 43.075,-42.425 44.075,-42.425 46.075,-42.425 47.075,-42.425 48.075,-42.425 49.075,-42.425 50.075,-42.425 55.075,-42.425 58.075,-42.425 59.075,-42.425 60.075,-42.425 61.075,-42.425 62.075,-42.425 63.075,-42.425 64.075,-42.425 1.075,-41.425 2.075,-41.425 3.075,-41.425 4.075,-41.425 5.075,-41.425 6.075,-41.425 7.075,-41.425 8.075,-41.425 9.075,-41.425 10.075,-41.425 13.075,-41.425 14.075,-41.425 15.075,-41.425 42.075,-41.425 43.075,-41.425 54.075,-41.425 55.075,-41.425 58.075,-41.425 59.075,-41.425 60.075,-41.425 61.075,-41.425 62.075,-41.425 63.075,-41.425 64.075,-41.425
NetC2_1: C2.1 C3.2 C6.2 C7.2 L1.2 R1.1 T1.1 T1.2@35.5,-26.04 U2.24 | length 54
  Top Layer w0.2: U2.24 v1(9,-22.79)
  Top Layer w0.5: R1.1 9.6,-9.725 10.467,-10.592 v1(10.82,-10.592)
  Bottom Layer w0.2: v1(9,-22.79) 9,-12.031 10.439,-10.592 v1(10.82,-10.592)
  Bottom Layer w0.5: v1(10.82,-10.592) 36.043,-10.592 37.77,-12.319 37.77,-19.453 v1(37.757,-19.466) v1@37.757,-22.916
  other v1: 35.475,-28.625 36.275,-28.625 37.075,-28.625 37.875,-28.625 35.875,-28.225 36.675,-28.225 37.475,-28.225 38.275,-28.225 37.075,-27.825 36.675,-27.425 37.475,-27.425 39.475,-27.425 40.275,-27.425 37.075,-27.025 39.875,-27.025 40.675,-27.025 36.675,-26.625 37.475,-26.625 39.475,-26.625 40.275,-26.625 37.075,-26.225 39.875,-26.225 40.675,-26.225 36.675,-25.825 37.475,-25.825 39.475,-25.825 40.275,-25.825 37.075,-25.425 39.875,-25.425 40.675,-25.425 36.675,-25.025 37.475,-25.025 39.475,-25.025 40.275,-25.025 37.075,-24.625 39.875,-24.625 40.675,-24.625 36.675,-24.225 37.475,-24.225 39.475,-24.225 40.275,-24.225 35.075,-23.825 35.875,-23.825 37.075,-23.825 37.875,-23.825 38.675,-23.825 39.875,-23.825 40.675,-23.825 35.475,-23.425 36.275,-23.425 37.475,-23.425 38.275,-23.425 39.075,-23.425 40.275,-23.425 35.075,-23.025 35.875,-23.025 36.675,-23.025 37.875,-23.025 38.675,-23.025 39.475,-23.025 40.675,-23.025 35.475,-22.625 36.275,-22.625 37.075,-22.625 38.275,-22.625 39.075,-22.625 39.875,-22.625 35.875,-22.225 36.675,-22.225 37.475,-22.225 38.675,-22.225 39.475,-22.225 40.275,-22.225 36.275,-21.825 37.075,-21.825 37.875,-21.825 39.075,-21.825 39.875,-21.825 40.675,-21.825 36.675,-21.425 37.475,-21.425 38.275,-21.425 39.475,-21.425 40.275,-21.425 37.075,-21.025 37.875,-21.025 38.675,-21.025 39.875,-21.025 40.675,-21.025 37.475,-20.625 38.275,-20.625 39.075,-20.625 40.275,-20.625 38.675,-20.225 39.475,-20.225 39.075,-19.825 39.875,-19.825 39.475,-19.425 39.875,-19.025
NetC2_2: C2.2 C4.2 L2.1 T1.6@26,-47.768 T1.7 T1.8@26.5,-52.96 T1.9@29.5,-52.96
NetC3_1: C3.1 R2.2 | length 2.7
  Top Layer w0.5: R2.2 36.907,-16.916 37.207,-16.616 37.207,-16.566 37.407,-16.366 C3.1
NetC8_1: C8.1 L1.1 Q9.1 Q9.3 U2.25 | length 44.2
  Top Layer w0.2: U2.25 8.5,-22.92 v1(8.5,-22.375)
  Bottom Layer w0.2: v1(8.5,-22.375) 8.5,-11.565 9.923,-10.142 38.742,-10.142 v1(39.7,-11.1)
NetC10_1: C10.1 R4.2
NetC10_2: C10.2 Q12.5 Q12.6 Q12.7 Q12.8 T1.9@33.5,-47.768 T1.10 T1.11 T1.12
NetC11_2: C11.2 R3.1 | length 1.4
  Top Layer w0.3: C11.2@3.207,-21.925 4.525,-21.925 R3.1
NetC12_2: C12.2 R6.1 U2.28 | length 17.1
  Top Layer w0.2: v1(5.65,-23.165) 5.994,-23.509 6.975,-23.509 7,-23.534 U2.28
  Top Layer w0.4: C12.2 v1(2.407,-11.252) R6.1
  Bottom Layer w0.4: v1(2.407,-11.252) 3.632,-11.252 5.65,-13.27 v1(5.65,-23.165)
NetC13_1: C13.1 T2.2 | length 23.1
  Top Layer w0.4: v1(44.375,-41.8) 45.374,-41.8 T2.2@45.384,-41.79 ; C13.1 62.8,-47.7 v1(63.4,-47.7)
  Bottom Layer w0.4: v1(44.375,-41.8) 52.747,-41.8 58.647,-47.7 v1(63.4,-47.7)
NetC13_2: C13.2 D5.K R9.1 R11.2 | length 4.6
  Top Layer w0.4: R11.2 60,-45 D5.K ; R11.2@60.012,-46.3 60.012,-47.663 60,-47.675 C13.2
NetC15_1: C15.1 R10.2 | length 1.7
  Top Layer w0.2: R10.2@12.2,-11 C15.1@12.2,-9.3
NetC15_2: C15.2 T2.1 | length 59.1
  Top Layer w0.2: C15.2 C15.2@14.021,-9.379
  Top Layer w0.4: C15.2 v1(14.58,-9.6) ; T2.1 v1(46.275,-36.71)
  Bottom Layer w0.3: v1(14.58,-9.6) 14.764,-9.785 39.604,-9.785 41.504,-11.684 41.504,-35.382 42.831,-36.71 v1(46.275,-36.71)
NetC17_1: C17.1 R17.2 | length 1.4
  Top Layer w0.8: R17.2 9.032,-31.259 9.032,-29.919 C17.1
NetC17_2: C17.2 C19.2 U2.13 | length 4
  Top Layer w0.2: U2.13 9,-28.966 9.117,-29.083 9.867,-29.083 10.655,-29.871 C17.2
  Top Layer w0.8: C17.2 10.682,-29.923 10.682,-31.255 C19.2
NetC18_2: C18.2 U2.11 | length 4.6
  Top Layer w0.2: C18.2 5.509,-30.457 6.35,-29.616 7.468,-29.616 8,-29.084 U2.11
NetD1_A: D1.A U1.11 | length 8.4
  Top Layer w0.3: v1(60.925,-30.675) U1.11
  Top Layer w0.4: D1.A v1(54.325,-31.25)
  Bottom Layer w0.3: v1(54.325,-31.25) 54.875,-30.7 60.873,-30.7 60.898,-30.675 v1(60.925,-30.675)
NetD3_K: D3.K L3.2 Q10.C
NetD4_K: D4.K Q11.4 U2.20 | length 27.3
  Top Layer w0.2: U2.20 v1(13.375,-25.25) ; Q11.4@29.527,-17.216 Q11.4
  Top Layer w0.3: Q11.4 Q11.4@29.555,-17.188
  Top Layer w0.4: D4.K v1(28.457,-17.196) 29.507,-17.196 Q11.4@29.527,-17.216
  Bottom Layer w0.2: v1(13.375,-25.25) 24.225,-14.4 27.456,-14.4 28.457,-15.401 v1(28.457,-17.196)
NetQ9_4: Q9.4 R3.2 U2.26 | length 52.2
  Top Layer w0.2: R3.2 7.135,-21.9 v1@8.025,-22.79 ; U2.26 v1(8,-22.79) ; v1@43.675,-10 v1@43.68,-9.995 ; Q9.4@44.56,-9.995 Q9.4
  Top Layer w0.4: v1(43.675,-9.991) Q9.4
  Bottom Layer w0.2: v1(8,-22.79) 8,-11.533 9.691,-9.842 13.628,-9.842 14.27,-9.2 40.086,-9.2 40.894,-10.008 43.658,-10.008 v1(43.675,-9.991)
NetQ10_B: Q10.B U2.23 | length 12.3
  Top Layer w0.2: Q10.B 9.525,-11.4 v1(9.525,-12.175) ; U2.23@9.5,-23.6 v1@9.5,-22.425
  Bottom Layer w0.2: v1@9.5,-22.425 9.525,-22.4 v1(9.525,-12.175)
  other v1: 9.5,-22.375
NetQ10_E: Q10.E R1.2 | length 1.8
  Top Layer w0.4: R1.2 7.55,-9.725 Q10.E
NetQ11_1: Q11.1 Q11.2 Q11.3 R8.2 U2.17 | length 21.2
  Top Layer w0.2: U2.17 10.156,-26.744 v1(11.614,-26.744)
  Bottom Layer w0.2: v1(11.614,-26.744) 11.614,-26.445 24.159,-13.9 v1(25.9,-13.9)
NetQ11_5: Q11.5 Q11.6 Q11.7 Q11.8 R2.1 T1.3 T1.4@29.5,-26.04
NetQ12_4: Q12.4 Q13.E Q14.E | length 5.9
  Top Layer w0.3: Q12.4@49.898,-50.023 Q13.E@51.452,-50.023 ; Q14.E@54.975,-51.9 Q14.E
  Top Layer w0.4: v1(54.9,-51.325) 54.9,-51.775 Q14.E
  Top Layer w0.5: Q12.4 Q12.4@49.898,-50.023 ; Q13.E@51.677,-50.023 Q13.E
  Bottom Layer w0.3: v1(51.7,-50.354) 52.671,-51.325 v1(54.9,-51.325)
NetQ13_B: Q13.B Q14.B R9.2 | length 5.8
  Top Layer w0.4: Q13.B Q14.B 56.1,-50 R9.2 R9.2@58.4,-47.675
NetR5_1: R5.1 R7.2 U2.14 | length 9.6
  Top Layer w0.2: U2.14 9.55,-28.35 9.6,-28.4 v1(10.1,-28.4) ; R7.2@16.9,-28.5 R7.2@17,-28.6
  Top Layer w0.4: v1(16.025,-28.375) 16.775,-28.375 R7.2@16.9,-28.5
  Top Layer w1: R7.2@17,-28.6 R5.1@19,-28.6
  Bottom Layer w0.2: v1(10.1,-28.4) 16,-28.4 v1(16.025,-28.375)
NetR5_2: R5.2 T1.5@26,-31.232 T1.6@23.5,-26.04 | length 10.9
  Top Layer w1: T1.6@23.5,-26.39 23.5,-28.732 25.725,-30.957 25.865,-30.957 26,-31.092 T1.5@26,-31.232
  Top Layer w1.25: R5.2 23.49,-26.4 23.5,-26.39 T1.6@23.5,-26.04
NetR10_1: R10.1 U2.18 | length 16.5
  Top Layer w0.2: U2.18 v1(10.825,-26.25) ; R10.1 R10.1@13.825,-11.425
  Bottom Layer w0.2: v1(10.825,-26.25) 10.825,-26.196 10.925,-26.096 10.925,-26.075 13.2,-23.8 v1(13.2,-11.4)
NetR12_2: R12.2 U2.15 | length 4.8
  Top Layer w0.2: U2.15 10.16,-27.76 10.639,-27.76 11.633,-28.754 11.633,-30.506 12.009,-30.882 12.009,-30.907 12.384,-31.282 R12.2
NetR13_2: R13.2 U2.12 | length 3.4
  Top Layer w0.2: R13.2 7.209,-30.306 8.5,-29.016 U2.12
NetR14_2: R14.2 U2.3 | length 3.9
  Top Layer w0.3: R14.2 3.421,-23.539 3.956,-23.539 5.667,-25.25 U2.3
NetR15_2: R15.2 U2.4 | length 3.5
  Top Layer w0.3: R15.2@3.207,-24.85 4,-24.85 4.9,-25.75 U2.4 ; R15.2@3.207,-24.85 R15.2
NetR16_2: R16.2 U2.10 | length 5.3
  Top Layer w0.2: R16.2 3.834,-31.282 4.209,-30.907 4.209,-30.882 5.78,-29.312 7.214,-29.312 7.5,-29.025 U2.10
NetTP1_1: TP1.1 U2.5 | length 4.6
  Top Layer w0.2: TP1.1@2,-26.875 2.125,-26.75 4.6,-26.75 5.1,-26.25 U2.5
NetU2_1: U2.1 U2.29
PoE_1: Q1.1 Q1.2 Q1.3 Q5.5-6-7-8 RPi1.1_PoE U1.15 | length 45.7
  Top Layer w0.3: U1.15 63.122,-27.475 63.602,-26.996 v1(63.602,-24.714)
  Top Layer w0.8: 61.493,-13.007 61.493,-9.836 62.77,-8.559 RPi1.1_PoE
  Top Layer w1.5: 56,-17.5 57,-17.5 61.493,-13.007
  Layer 2 w0.8: 61.493,-13.007 61.493,-9.836 RPi1.1_PoE@62.77,-8.559
  Layer 2 w1.5: v1(56.825,-17.501) 57,-17.5 61.493,-13.007
  Bottom Layer w0.3: RPi1.1_PoE 62.77,-8.426 61.239,-9.957 61.239,-14.478 62.941,-16.18 62.941,-18.948 63.602,-19.609 v1(63.602,-24.714)
  other v1: 56.825,-17.983 56.825,-17.043
PoE_2: Q2.1 Q2.2 Q2.3 Q6.5-6-7-8 RPi1.2_PoE U1.2 | length 26.3
  Top Layer w0.2: Q6.5-6-7-8@55.453,-8.481 Q6.5-6-7-8@55.453,-8.467
  Top Layer w0.3: U1.2 v1(60.925,-24.825)
  Top Layer w1: 56,-8.5 56.13,-8.37
  Top Layer w1.5: 56.13,-8.37 RPi1.2_PoE
  Layer 1 w0.3: RPi1.2_PoE@59.9,-8.37 RPi1.2_PoE 60.265,-8.37 61.275,-9.38 61.275,-14.976 60.925,-15.326 v1(60.925,-16.45)
  Layer 2 w1.5: v1(56.825,-8.371) RPi1.2_PoE
  Bottom Layer w0.3: v1(60.925,-24.825) v1(60.925,-16.45)
  other v1: 56.825,-8.853 56.825,-7.913
PoE_3: Q3.1 Q3.2 Q3.3 Q7.5-6-7-8 RPi1.3_PoE U1.3 | length 25.7
  Top Layer w0.3: U1.3 v1(60.275,-24.825)
  Top Layer w1.5: Q7.5-6-7-8 Q7.5-6-7-8 57.98,-13.16 RPi1.3_PoE
  Layer 1 w0.3: RPi1.3_PoE@59.9,-10.91 60.275,-11.285 v1(60.275,-17.125)
  Layer 2 w1.5: v1(56.825,-13.161) 57.98,-13.16 RPi1.3_PoE
  Bottom Layer w0.3: v1(60.275,-24.825) v1(60.275,-17.125)
  other v1: 56.825,-13.643 56.825,-12.704
PoE_4: Q4.1 Q4.2 Q4.3 Q8.5-6-7-8 RPi1.4_PoE U1.6 | length 38.5
  Top Layer w0.3: 55.807,-22.662 57.6,-24.454 57.6,-27.299 57.776,-27.475 U1.6
  Top Layer w0.8: Q8.5-6-7-8 Q8.5-6-7-8@55.453,-22.66
  Top Layer w1.5: Q8.5-6-7-8 Q8.5-6-7-8 ; Q8.5-6-7-8@55.453,-22.66 57.324,-22.66 63.4,-16.585 63.4,-11.54 RPi1.4_PoE
  Layer 2 w1.5: v1(56.825,-22.661) 57.324,-22.66 63.4,-16.585 63.4,-11.54 RPi1.4_PoE
  other v1: 56.825,-23.143 56.825,-22.204
PoE_V_Out: C5.1 C14.2 L2.2 P1.1 P1.3 Q14.C | length 58.8
  Top Layer w0.3: v1(56.591,-50.95) Q14.C ; C14.2 C14.2@56.95,-54.1
  Top Layer w0.4: C14.2 56.962,-53.988 56.962,-51.013 Q14.C
  Bottom Layer w0.3: P1.1 8.026,-49.026 8.026,-50.8 9.169,-51.943 55.575,-51.943 56.568,-50.95 v1(56.591,-50.95)
PoE_VCC: C9.1 L3.1 U2.6 U2.7 U2.8 U2.9 U2.21 | length 21.1
  Top Layer w0.3: U2.6 U2.7 U2.8 6.35,-28.099 6.526,-28.275 6.975,-28.275 7,-28.3 U2.9 ; U2.21 10.9,-24.75 12.1,-23.55 12.1,-23.5 C9.1@12.4,-23.2
  Top Layer w0.4: v1(5.65,-27.25) U2.7
  Top Layer w0.9: L3.1 10.55,-19.925 10.9,-20.275 v1(10.9,-21.7) 12.4,-23.2 C9.1
  Bottom Layer w0.5: v1(5.65,-27.25) 6.223,-26.677 6.223,-25.222 7.925,-23.52 9.779,-23.52 10.9,-22.399 v1(10.9,-21.7)
PoEGND: C1.1 C6.1 C7.1 C8.2 C9.2 C11.1 C12.1 C16.1 C18.1 C19.1 D2.A D3.A D4.A Q5.1 Q5.2 Q5.3 Q6.1 Q6.2 Q6.3 Q7.1 Q7.2 Q7.3 Q8.1 Q8.2 Q8.3 R7.1 R8.1 R12.1 R13.1 R14.1 R15.1 R16.1 R17.1 T1.4@28.5,-31.232 T1.5@26.5,-26.04 T2.4 TP2.1 U1.9 U2.2 U2.16 U2.19 | length 34.5
  Top Layer w0.2: 5.65,-24.25 5.688,-24.288 5.688,-24.638 5.8,-24.75 U2.2 ; U2.16 11.038,-27.25 v1(11.05,-27.238)
  Top Layer w0.3: 5.65,-24.25 6.35,-24.25 6.975,-24.25 8.075,-25.35 ; U2.19@10.15,-25.75 11.85,-25.75 12.4,-26.3 C9.2
  Top Layer w0.4: v1(54.259,-20.575) Q5.1 ; v1(54.259,-15.75) Q7.1 ; v1(54.259,-11.075) Q6.1 ; v1(54.92,-15.77) Q7.2 ; v1(54.92,-20.575) Q5.2 ; v1(54.92,-11.075) Q6.2 ; v1(55.58,-20.575) Q5.3 ; v1(55.58,-15.77) Q7.3 ; v1(55.58,-11.075) Q6.3
  Bottom Layer w0.2: v1(11.05,-27.238) 11.055,-27.233 11.055,-26.738 11.281,-26.511 11.281,-26.219 24.075,-13.425 25.179,-13.425 v1(25.704,-12.9)
  other v1: 42.075,-37.425 43.075,-37.425 46.075,-37.425 47.075,-37.425 48.075,-37.425 49.075,-37.425 50.075,-37.425 53.075,-37.425 54.075,-37.425 55.075,-37.425 58.075,-37.425 59.075,-37.425 60.075,-37.425 61.075,-37.425 62.075,-37.425 63.075,-37.425 64.075,-37.425 47.075,-36.425 48.075,-36.425 49.075,-36.425 50.075,-36.425 53.075,-36.425 54.075,-36.425 55.075,-36.425 58.075,-36.425 59.075,-36.425 60.075,-36.425 61.075,-36.425 62.075,-36.425 63.075,-36.425 64.075,-36.425 43.075,-35.425 46.075,-35.425 47.075,-35.425 48.075,-35.425 49.075,-35.425 50.075,-35.425 53.075,-35.425 54.075,-35.425 55.075,-35.425 56.075,-35.425 57.075,-35.425 58.075,-35.425 59.075,-35.425 60.075,-35.425 61.075,-35.425 62.075,-35.425 63.075,-35.425 64.075,-35.425 43.075,-34.425 44.075,-34.425 45.075,-34.425 46.075,-34.425 47.075,-34.425 48.075,-34.425 49.075,-34.425 50.075,-34.425 51.075,-34.425 52.075,-34.425 53.075,-34.425 54.075,-34.425 55.075,-34.425 56.075,-34.425 57.075,-34.425 58.075,-34.425 59.075,-34.425 60.075,-34.425 61.075,-34.425 62.075,-34.425 63.075,-34.425 64.075,-34.425 43.075,-33.425 44.075,-33.425 45.075,-33.425 46.075,-33.425 47.075,-33.425 48.075,-33.425 49.075,-33.425 50.075,-33.425 51.075,-33.425 52.075,-33.425 53.075,-33.425 54.075,-33.425 55.075,-33.425 56.075,-33.425 57.075,-33.425 58.075,-33.425 59.075,-33.425 60.075,-33.425 61.075,-33.425 62.075,-33.425 63.075,-33.425 64.075,-33.425 43.075,-32.425 44.075,-32.425 45.075,-32.425 46.075,-32.425 47.075,-32.425 48.075,-32.425 49.075,-32.425 50.075,-32.425 51.075,-32.425 54.075,-32.425 55.075,-32.425 56.075,-32.425 57.075,-32.425 58.075,-32.425 59.075,-32.425 60.075,-32.425 61.075,-32.425 62.075,-32.425 63.075,-32.425 64.075,-32.425 43.075,-31.425 44.075,-31.425 45.075,-31.425 46.075,-31.425 47.075,-31.425 48.075,-31.425 49.075,-31.425 50.075,-31.425 55.075,-31.425 56.075,-31.425 57.075,-31.425 58.075,-31.425 59.075,-31.425 60.075,-31.425 61.075,-31.425 62.075,-31.425 63.075,-31.425 64.075,-31.425 43.075,-30.425 44.075,-30.425 45.075,-30.425 46.075,-30.425 47.075,-30.425 48.075,-30.425 49.075,-30.425 63.075,-30.425 64.075,-30.425 43.075,-29.425 44.075,-29.425 45.075,-29.425 46.075,-29.425 47.075,-29.425 48.075,-29.425 55.075,-29.425 56.075,-29.425 57.075,-29.425 58.075,-29.425 59.075,-29.425 64.075,-29.425 43.075,-28.425 44.075,-28.425 45.075,-28.425 46.075,-28.425 47.075,-28.425 56.075,-28.425 57.075,-28.425 44.075,-27.425 47.075,-27.425 54.075,-27.425 55.075,-27.425 56.075,-27.425 44.075,-26.425 47.075,-26.425 55.075,-26.425 56.075,-26.425 44.075,-25.425 47.075,-25.425 54.259,-25.275 54.92,-25.27 55.58,-25.27 16.075,-24.425 17.075,-24.425 18.075,-24.425 19.075,-24.425 20.075,-24.425 21.075,-24.425 22.075,-24.425 44.075,-24.425 46.075,-24.425 47.075,-24.425 17.075,-23.425 18.075,-23.425 19.075,-23.425 20.075,-23.425 21.075,-23.425 22.075,-23.425 23.075,-23.425 44.075,-23.425 47.075,-23.425 14.075,-22.425 18.075,-22.425 19.075,-22.425 20.075,-22.425 21.075,-22.425 22.075,-22.425 23.075,-22.425 24.075,-22.425 44.075,-22.425 47.075,-22.425 14.075,-21.425 15.075,-21.425 19.075,-21.425 20.075,-21.425 21.075,-21.425 22.075,-21.425 23.075,-21.425 24.075,-21.425 25.075,-21.425 47.075,-21.425 14.075,-20.425 15.075,-20.425 16.075,-20.425 20.075,-20.425 21.075,-20.425 22.075,-20.425 23.075,-20.425 24.075,-20.425 25.075,-20.425 26.075,-20.425 27.075,-20.425 28.075,-20.425 46.075,-20.425 14.075,-19.425 15.075,-19.425 16.075,-19.425 17.075,-19.425 21.075,-19.425 22.075,-19.425 23.075,-19.425 24.075,-19.425 25.075,-19.425 26.075,-19.425 28.075,-19.425 14.075,-18.425 15.075,-18.425 16.075,-18.425 17.075,-18.425 18.075,-18.425 22.075,-18.425 23.075,-18.425 24.075,-18.425 25.075,-18.425 26.075,-18.425 27.075,-18.425 28.075,-18.425 14.075,-17.425 15.075,-17.425 16.075,-17.425 17.075,-17.425 18.075,-17.425 19.075,-17.425 23.075,-17.425 24.075,-17.425 25.075,-17.425 26.075,-17.425 14.075,-16.425 15.075,-16.425 16.075,-16.425 17.075,-16.425 18.075,-16.425 19.075,-16.425 20.075,-16.425 24.075,-16.425 25.075,-16.425 26.075,-16.425 27.075,-16.425 14.075,-15.425 15.075,-15.425 16.075,-15.425 17.075,-15.425 18.075,-15.425 19.075,-15.425 20.075,-15.425 21.075,-15.425 25.075,-15.425 26.075,-15.425 27.075,-15.425 34.075,-15.425 35.075,-15.425 36.075,-15.425 14.075,-14.425 15.075,-14.425 16.075,-14.425 17.075,-14.425 18.075,-14.425 19.075,-14.425 20.075,-14.425 21.075,-14.425 22.075,-14.425 34.075,-14.425 35.075,-14.425 36.075,-14.425 15.075,-13.425 16.075,-13.425 17.075,-13.425 18.075,-13.425 19.075,-13.425 20.075,-13.425 21.075,-13.425 22.075,-13.425 23.075,-13.425 33.075,-13.425 34.075,-13.425 35.075,-13.425 36.075,-13.425 14.075,-12.425 15.075,-12.425 16.075,-12.425 17.075,-12.425 18.075,-12.425 19.075,-12.425 20.075,-12.425 21.075,-12.425 22.075,-12.425 23.075,-12.425 24.075,-12.425 25.075,-12.425 33.075,-12.425 34.075,-12.425 15.075,-11.425 16.075,-11.425 17.075,-11.425 18.075,-11.425 19.075,-11.425 20.075,-11.425 21.075,-11.425 22.075,-11.425 23.075,-11.425 24.075,-11.425 25.075,-11.425 33.075,-11.425 34.075,-11.425
TG12: Q1.4 U1.16 | length 19.7
  Top Layer w0.3: Q1.4@52.25,-17.519 52.275,-17.494 v1(52.275,-16.95) ; U1.16 v1(63.075,-26.825)
  Layer 1 w0.3: v1(52.275,-16.95) 54.75,-16.95 57.625,-19.825 v1(62.125,-19.825)
  Bottom Layer w0.3: v1(62.125,-19.825) 62.125,-25.368 63.075,-26.318 v1(63.075,-26.825)
TG36: Q2.4 U1.1 | length 24.4
  Top Layer w0.3: v1(52.15,-7.425) 52.15,-7.974 Q2.4 ; U1.1 v1(61.575,-24.825)
  Bottom Layer w0.3: v1(52.15,-7.425) 54.425,-7.425 56.355,-9.355 56.355,-10.845 61.575,-16.065 v1(61.575,-24.825)
TG45: Q3.4 U1.4 | length 20.4
  Top Layer w0.3: v1(52.15,-12.125) 52.15,-12.669 Q3.4 ; U1.4 v1(59.625,-24.825)
  Bottom Layer w0.3: v1(52.15,-12.125) 57.032,-12.125 59.625,-14.718 v1(59.625,-24.825)
TG78: Q4.4 U1.5 | length 11.9
  Top Layer w0.3: v1(52.175,-21.625) 52.175,-22.195 Q4.4 ; v1@58.1,-26.8 v1(58.125,-26.825) U1.5
  Bottom Layer w0.3: v1(52.175,-21.625) 57.236,-21.625 58.125,-22.514 v1(58.125,-26.825)
VPort: C1.2 D1.K D2.K Q1.5-6-7-8 Q2.5-6-7-8 Q3.5-6-7-8 Q4.5-6-7-8 Q9.5-6-7-8 R6.2 U1.10 U1.12 | length 54.8
  Top Layer w0.3: U1.10 60.275,-30.148 60.3,-30.173 v1@60.3,-30.2 ; U1.12 61.575,-30.148 61.6,-30.173 v1@61.6,-30.2
  Top Layer w1: R6.2 v1(3.886,-8.175)
  Layer 1 w1: v1(3.886,-8.175) 4.508,-8.797 v1(46.533,-8.797)
  Bottom Layer w0.3: v1(52.4,-30.2) v1(60.275,-30.2) v1(61.575,-30.2) v1@61.6,-30.2
pads on no net: Q9.2 T1.2@33.5,-31.232 T1.8@31,-47.768 U2.22 U2.27
copper on no net:
  other v2: 3.5,-52.5 61.5,-52.5 3.5,-3.5 61.5,-3.5

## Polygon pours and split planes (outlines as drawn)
PoEGND on Top Layer "Top Layer-PoEGND" (solid, remove dead copper, pour order 137): 51.054,-37.871 65,-37.871 65,-25.984 55.91,-25.984 55.91,-24.132 54.06,-24.132 53.535,-24.657 53.535,-25.457 53.096,-25.897 51.41,-25.897 51.41,-6.782 0,-6.782 0,-37.871
NetC2_1 on Top Layer "Top Layer-NetC3_1" (solid, remove dead copper, pour order 94): 35.265,-32.107 36.735,-32.107 36.735,-30.357 39.401,-27.691 43.002,-27.691 43.002,-22.504 45.1,-20.407 45.1,-17.7 40.5,-17.7 39.201,-18.999 36.932,-18.999 36.932,-20.65 34.86,-22.722 34.86,-27.748 35.265,-28.153
GND on Top Layer "GND" (solid, remove dead copper, pour order 119): 3,-56 cw(c3,-53) 0,-53 0,-40.488 65,-40.488 65,-53 cw(c62,-53) 62,-56
PoE_V_Out on Top Layer "POE_V_OUT_L01_P065" (solid, pour order 65): 13.97,-51.175 13.97,-47.52 11.789,-45.339 0,-45.339 0,-49.05 5.9,-49.05 8.025,-51.175
PoE_4 on Top Layer "POE_4_L01_P126" (solid, remove dead copper, pour order 126): 51.685,-22.641 51.685,-24.398 53.234,-24.398 54.132,-23.5 56.444,-23.5 56.444,-22.027 56.444,-21.265 54.056,-21.265 52.68,-22.641
PoE_1 on Top Layer "POE_1_L01_P125" (solid, remove dead copper, pour order 125): 51.685,-17.956 51.685,-19.713 53.234,-19.713 54.132,-18.814 56.444,-18.814 56.444,-17.341 56.444,-16.579 54.056,-16.579 52.68,-17.956
PoE_3 on Top Layer "POE_3_L01_P124" (solid, remove dead copper, pour order 124): 51.685,-13.141 51.685,-14.898 53.234,-14.898 54.132,-14 56.444,-14 56.444,-12.527 56.444,-11.765 54.056,-11.765 52.68,-13.141
PoE_2 on Top Layer "POE_2_L01_P123" (solid, remove dead copper, pour order 123): 51.685,-8.446 51.685,-10.203 53.234,-10.203 54.132,-9.305 56.444,-9.305 56.444,-7.832 56.444,-7.07 54.056,-7.07 52.68,-8.446
NetQ11_5 on Top Layer "Top Layer-NetQ9_5" (solid, remove dead copper, pour order 70): 34.664,-19.761 34.664,-18.441 29.107,-18.441 28.593,-18.956 28.593,-28.685 30.265,-30.357 30.265,-32.107 31.735,-32.107 31.735,-29.29 33.235,-27.79 33.235,-24.652 33.807,-24.079 33.807,-20.618
NetC2_2 on Top Layer "Top Layer-NetC3_2" (solid, remove dead copper, pour order 69): 9.163,-52.5 9.163,-56.024 30.15,-56.017 30.15,-50.165 29.21,-50.165 29.21,-46.863 25.273,-46.863 24.435,-47.701 20.5,-47.701 20.5,-40.6 15.5,-40.6 15.5,-47.975 17.043,-49.518 17.043,-50.957 15.5,-52.5
NetC10_2 on Top Layer "Top Layer-NetC22_2" (solid, remove dead copper, pour order 67): 31.814,-52.568 31.814,-55.99 48.629,-55.99 48.629,-49.545 46.292,-49.545 45.85,-49.103 45.85,-47.701 41.732,-47.701 40.859,-46.828 32.754,-46.828 32.754,-50.133 31.814,-50.133
NetD3_K on Top Layer "NETD3_K_L01_P026" (solid, pour order 26): 5.65,-16.025 5.65,-14.425 7.2,-12.875 12.05,-12.875 12.05,-13.725 11.35,-14.425 11.35,-16.025
NetQ11_1 on Top Layer "NETQ11_1_L01_P013" (solid, pour order 13): 30.023,-16.772 33.222,-16.772 33.228,-15.047 31.333,-13.152 27.6,-13.152 25.999,-13.152 25.999,-14.448 28.494,-14.448 30.023,-15.977
NetC8_1 on Top Layer "NETC8_1_L01_P006" (solid, pour order 6): 45.11,-7.798 45.11,-15.3 40.6,-15.3 37.619,-12.319 35.255,-12.319 35.255,-9.855 38.462,-9.855 40.519,-7.798
VPort on Top Layer "VPORT_L01_P005" (solid, pour order 5): 52.9,-32.2 52.9,-25.9 51.4,-24.4 51.4,-7.798 45.669,-7.798 45.669,-11.369 46.9,-12.6 46.9,-20.5 47.75,-21.35 47.75,-28.05 51.9,-32.2
NetC10_1 on Top Layer "NETC10_1_L01_P000" (solid, remove dead copper, pour order 0): 44.15,-43.85 44.15,-44.95 45.95,-44.95 46.7,-45.7 46.7,-47.8 48.5,-47.8 48.5,-44.1 46.7,-44.1 46.45,-43.85
PoEGND on Bottom Layer "Top Layer-PoEGND" (solid, remove dead copper, pour order 140): 51.054,-37.871 65,-37.871 65,-25.984 55.91,-25.984 55.91,-24.132 54.06,-24.132 53.535,-24.657 53.535,-25.457 53.008,-25.984 51.41,-25.984 51.41,-21.006 55.91,-21.006 55.91,-19.431 51.41,-19.431 51.41,-16.205 55.91,-16.205 55.91,-14.63 51.41,-14.63 51.41,-11.506 55.91,-11.506 55.91,-9.931 51.41,-9.931 51.41,-6.782 0,-6.782 0,-37.871
NetC2_1 on Bottom Layer "NETC2_1_L04_P021" (solid, pour order 21): 15.75,-37.925 15.775,-37.9 20.525,-37.9 20.612,-32.388 23.95,-29.05 40.2,-29.05 41.6,-27.65 41.6,-20.2 40.2,-18.8 36.6,-18.8 34.05,-21.35 25.9,-21.35 15.75,-31.5
GND on Bottom Layer "GND" (solid, remove dead copper, pour order 42): 3,-56 cw(c3,-53) 0,-53 0,-40.488 65,-40.488 65,-53 cw(c62,-53) 62,-56
PoEGND on Layer 1 "Layer 1-PoEGND" (solid, remove dead copper, pour order 136): 51.054,-37.871 65,-37.871 65,-25.984 55.91,-25.984 55.91,-24.126 54.066,-24.126 53.535,-24.657 53.535,-25.457 53.008,-25.984 51.41,-25.984 51.41,-21 55.9,-21 55.9,-19.434 51.41,-19.434 51.41,-16.195 55.9,-16.195 55.9,-14.629 51.41,-14.629 51.41,-11.5 55.9,-11.5 55.9,-9.934 51.41,-9.934 51.41,-6.782 0,-6.782 0,-37.871
NetC2_1 on Layer 1 "Top Layer-NetC3_1" (solid, remove dead copper, pour order 71): 35.265,-32.107 36.735,-32.107 36.735,-30.357 39.401,-27.691 43.002,-27.691 43.002,-22.504 45.1,-20.407 45.1,-17.7 40.5,-17.7 39.201,-18.999 36.932,-18.999 36.932,-20.65 34.86,-22.722 34.86,-27.748 35.265,-28.153
GND on Layer 1 "GND" (solid, remove dead copper, pour order 117): 3,-56 cw(c3,-53) 0,-53 0,-40.488 65,-40.488 65,-53 cw(c62,-53) 62,-56
PoEGND on Layer 2 "Layer 2-PoEGND" (solid, remove dead copper, pour order 138): 51.054,-37.871 65,-37.871 65,-25.984 55.91,-25.984 55.91,-24.126 54.066,-24.126 53.535,-24.657 53.535,-25.457 53.008,-25.984 51.41,-25.984 51.41,-21 55.9,-21 55.9,-19.434 51.41,-19.434 51.41,-16.195 55.9,-16.195 55.9,-14.629 51.41,-14.629 51.41,-11.5 55.9,-11.5 55.9,-9.934 51.41,-9.934 51.41,-6.782 0,-6.782 0,-37.871
NetC2_1 on Layer 2 "Top Layer-NetC3_1" (solid, remove dead copper, pour order 45): 35.265,-32.107 36.735,-32.107 36.735,-30.357 39.401,-27.691 43.002,-27.691 43.002,-22.504 45.1,-20.407 45.1,-17.7 40.5,-17.7 39.201,-18.999 36.932,-18.999 36.932,-20.65 34.86,-22.722 34.86,-27.748 35.265,-28.153
GND on Layer 2 "GND" (solid, remove dead copper, pour order 95): 3,-56 cw(c3,-53) 0,-53 0,-40.488 65,-40.488 65,-53 cw(c62,-53) 62,-56

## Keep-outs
Top Layer:
  rectangle: 5.65,-19.125 11.35,-16.025
  rectangle: 40.6,-19.9 47.4,-13.1
Keep-Out Layer:
  rectangle: 0,-40.4 65,-38.1

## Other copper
Bottom Layer:
  pour cut-out: 11.842,-27.508 13.777,-25.573 24.901,-14.448 27.508,-14.448 27.508,-12.9 23.9,-12.9 11.738,-25.062 11.738,-25.753 10.825,-26.665 10.825,-27.508
Multi-Layer:
  pour cut-out: 20.5,-31.965 20.5,-46.965 41.5,-46.965 41.5,-31.965

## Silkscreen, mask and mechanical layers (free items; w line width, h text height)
Mechanical 12:
  the board outline again, w0.4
